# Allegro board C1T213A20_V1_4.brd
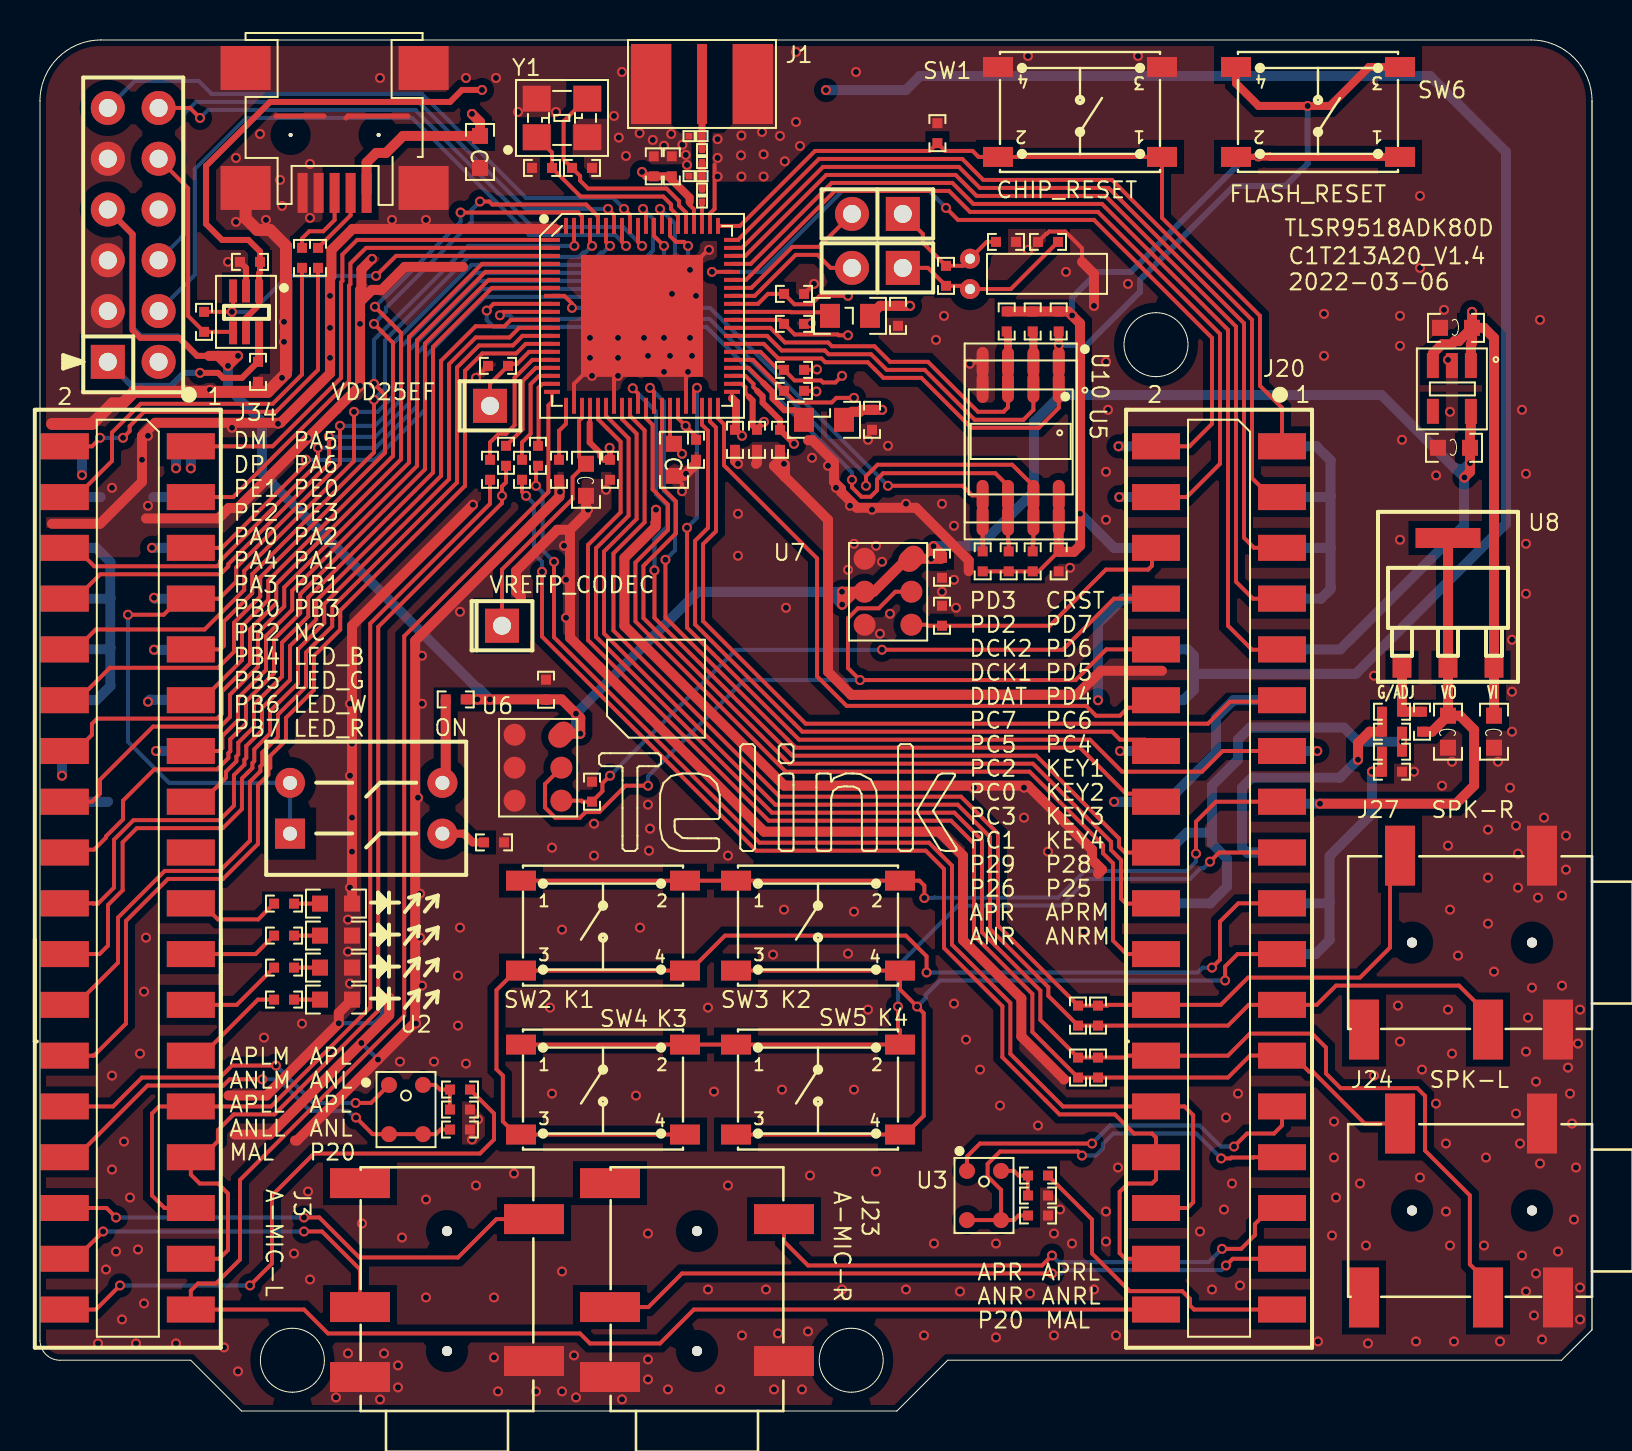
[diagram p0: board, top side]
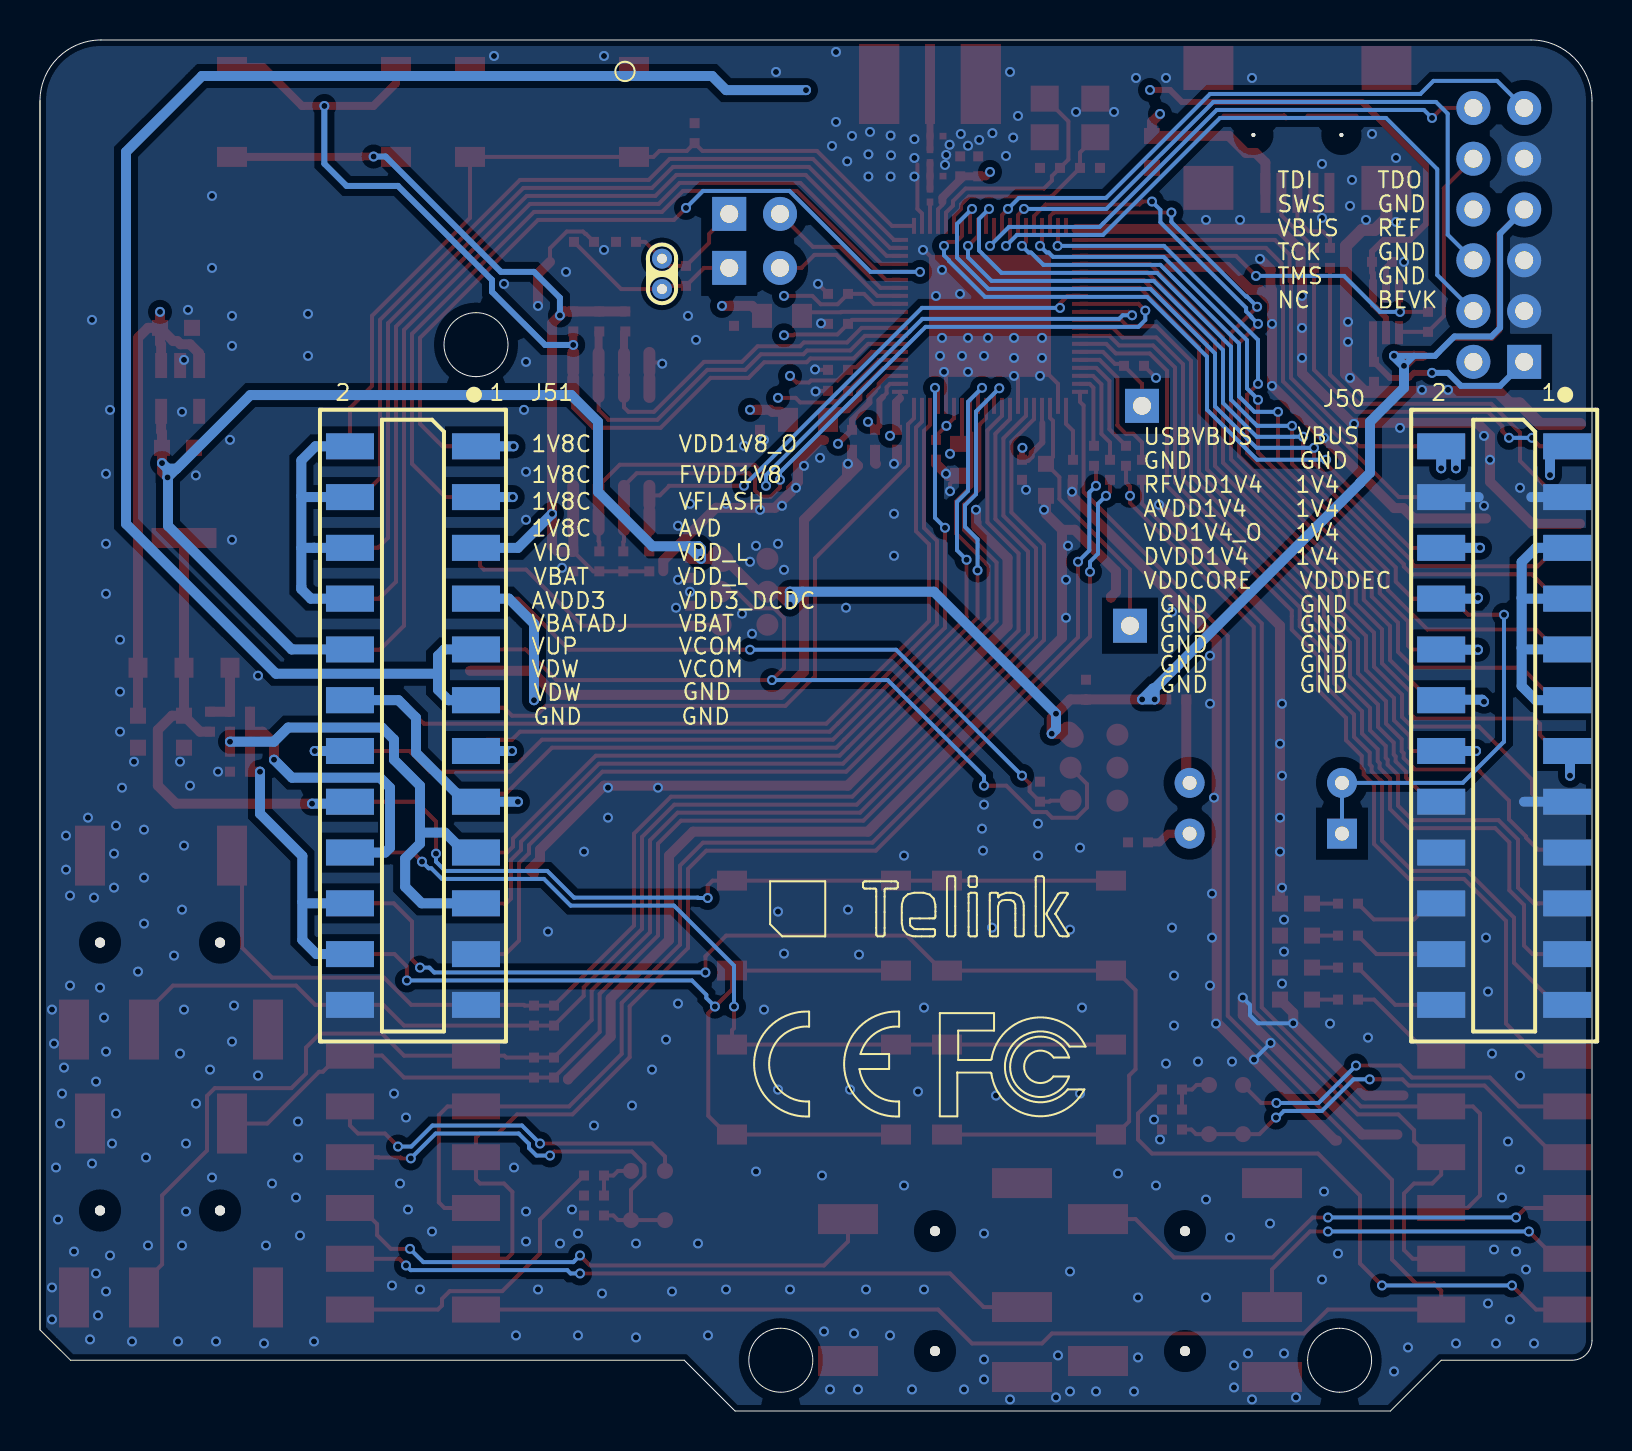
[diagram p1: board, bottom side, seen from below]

Outline 77.6 x 68.58 mm; copper layers: TOP, GND, POWER, BOTTOM. Coordinates in mm from the lower left corner of the outline.
Outline path: 77.6,65.53 arc(76.71,67.69) 74.55,68.58 3.05,68.58 arc(0.89,67.69) 0,65.53 0,3.54 arc(0.29,2.83) 1,2.54 7.54,2.54 10.08,0 42.85,0 45.39,2.54 76.08,2.54 77.6,4.06 ; 77.6,65.53 77.6,4.06 ; 77.6,65.53 77.6,4.06 ; 12.62,4.14 arc(14.22,2.54) 12.62,0.94 arc(11.02,2.54) 12.62,4.14 ; 40.56,4.14 arc(42.16,2.54) 40.56,0.94 arc(38.96,2.54) 40.56,4.14 ; 55.8,54.94 arc(57.4,53.34) 55.8,51.74 arc(54.2,53.34) 55.8,54.94

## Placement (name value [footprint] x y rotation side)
C1  NC  [0402]  27.1 62.18 180 top
C2  0.1uF  [0402]  31.59 62.26 90 top
C3  2.2uF  [0402]  30.69 62.26 90 top
C4  NC  [0402]  25.1 62.18 0 top
C6  1.8pF  [0201]  32.77 61.77 0 top
C7  1pF  [0201]  32.77 63.77 0 top
C8  NC  [0402]  50.4 58.48 0 top
C9  NC  [0402]  48.3 58.48 180 top
C10  1uF  [0402]  44.87 63.92 90 top
C11  1uF  [0402]  37.7 55.88 0 top
C12  1uF  [0402]  42.9 54.78 270 top
C13  1uF  [0402]  37.7 54.38 0 top
C14  1uF  [0402]  22.9 52.28 180 top
C15  1uF  [0402]  37 48.58 270 top
C16  1uF  [0402]  37.7 52.08 0 top
C17  1uF  [0402]  22.5 47.08 90 top
C19  1uF  [0402]  23.3 47.78 90 top
C21  1uF  [0402]  35.85 48.58 270 top
C22  1uF  [0402]  37.7 51.03 0 top
C23  0.1uF  [0402]  25.3 36.08 90 top
C24  1uF  [0402]  24.1 47.08 90 top
C25  1uF  [0402]  24.9 47.78 90 top
C26  0.1uF  [0402]  45.1 42.18 270 top
C27  1uF  [0402]  25.95 47.08 270 top
C29  1uF  [0402]  41.6 49.58 270 top
C30  10uF  [0603C]  27.3 46.58 270 top
C31  1uF  [0402]  28.5 47.08 270 top
C32  NC/10uF  [0603C]  31.7 47.58 270 top
C33  1uF  [0402]  32.8 48.08 270 top
C34  NC  [0402]  52.9 17.18 90 top
C36  10uF  [0603C]  22 62.98 270 top
C37  NC  [0402]  52.9 19.78 90 top
C38  1uF  [0402]  50.94 42.5 270 top
C39  0.1uF  [0402]  10.5 57.48 180 top
C40  0.1uF  [0402]  10.9 51.98 270 top
C41  1uF  [0402]  21 15.08 0 top
C42  1uF  [0402]  49.9 10.78 0 top
C44  10uF  [0603C]  72.7 33.98 270 top
C45  10uF  [0603C]  70.4 33.98 270 top
C48  10uF  [0603C]  70.7 48.18 180 top
C49  10uF  [0603C]  70.8 54.18 180 top
C62  1uF  [0402]  34.75 48.58 270 top
D1  Blue  [0603-LED]  14.8 25.38 0 top
D2  Green  [0603-LED]  14.8 23.78 0 top
D3  White  [0603-LED]  14.8 22.18 0 top
D4  Red  [0603-LED]  14.8 20.58 0 top
J1  RFIN  [SMA-H]  33.1 66.38 270 top
J3  AIL1  [PJ-327]  20.35 0 180 top
J20  HEADER 18X2  [SMD254M-2X18_RX1_30Y2_40]  58.95 21.59 90 top
J23  AIR1  [PJ-327]  32.85 0 180 top
J24  AOPHR  [PJ-327]  77.6 10.03 270 top
J26  USB_MiniABF  [USB-MINI-F5]  14.73 60.93 180 top
J27  AOPHR  [PJ-327]  77.6 23.43 270 top
J30  32K  [HDR254F-1X2X850]  40.6 57.18 0 top
J31  32K  [HDR254F-1X2X850]  40.6 59.88 0 top
J34  HEADER 18X2  [SMD254M-2X18_RX1_30Y2_40]  4.39 21.59 90 top
J50  HEADER 12X2  [SMD254M-2X12_RX1_30Y2_40]  4.39 34.29 90 bottom
J51  HEADER 12X2  [SMD254M-2X12_RX1_30Y2_40]  58.95 34.29 90 bottom
J52  VDD25EF  [HDR254F-1X1X850]  22.5 50.28 0 top
J53  VREFP_CODEC  [HDR254F-1X1X850]  23.1 39.28 0 top
J56  JTAG  [HDR254F-2X6X850]  3.39 65.18 270 top
J57  DIP_2X2  [DIPSWITCH_2P54_7P62_2X2]  16.31 30.15 270 top
L1  2.4nH  [0201]  33.1 62.77 90 top
L3  10uH  [0805L]  40.5 54.78 0 top
L4  10uH  [0805L]  39.2 49.58 0 top
L5  2.4nH  [0201]  33.1 60.8 90 top
R1  NC  [0402]  45.3 56.78 90 top
R2  2.2K  [0402]  21 16.08 180 top
R3  2.2K  [0402]  21 14.08 180 top
R4  2.2K  [0402]  49.9 11.78 180 top
R5  2.2K  [0402]  49.9 9.78 180 top
R6  NC  [0402]  51.9 17.18 90 top
R7  NC  [0402]  51.9 19.78 90 top
R8  33  [0402R]  13.9 57.68 270 top
R9  100K  [0402]  27.6 30.98 270 top
R10  33  [0402R]  13.1 57.68 270 top
R11  4.7K  [0402]  48.34 54.5 270 top
R12  NC  [0402]  49.64 54.5 270 top
R13  4.7K  [0402]  50.94 54.5 270 top
R14  4.7K  [0402]  49.64 42.5 90 top
R15  NC  [0402]  48.44 42.5 90 top
R16  NC  [0402]  47.14 42.5 90 top
R17  0R  [0402R]  8.2 54.48 270 top
R18  1M  [0402]  22.7 28.44 180 top
R19  100K  [0402]  45.1 39.78 270 top
R20  1K  [0402]  12.2 20.58 0 top
R21  1K  [0402]  12.2 23.78 0 top
R22  1K  [0402]  12.2 25.38 0 top
R23  1K  [0402]  12.2 22.18 0 top
R24  1K  [0402]  69.1 34.48 270 top
R25  430R  [0402]  67.6 34.98 180 top
R26  1.15K  [0402]  67.6 33.98 0 top
R27  787R  [0402]  67.6 32.98 180 top
R28  464R  [0402]  67.6 31.98 0 top
R29  1K  [0402]  20.79 35.6 180 top
SW1  SW4PIN_4.5x4.5  [SW_6X6_SMD]  52 64.98 180 top
SW2  Key1  [SW_6X6_SMD]  28.15 24.28 0 top
SW3  Key2  [SW_6X6_SMD]  38.9 24.28 0 top
SW4  Key3  [SW_6X6_SMD]  28.15 16.08 0 top
SW5  Key4  [SW_6X6_SMD]  38.9 16.08 0 top
SW6  FRST  [SW_6X6_SMD]  63.9 64.98 180 top
U1  TLSR9518A  [QFN_9X9_80PIN_0P4_6P10X6P10]  30.1 54.78 0 top
U2  WMM7037AT2  [GA_BFA423_A83]  18.3 15.08 0 top
U3  WMM7037AT2  [GA_BFA423_A83]  47.2 10.78 0 top
U4  NC/TXS0101  [SC70-6]  10.3 54.98 180 top
U5  P25Q8OU  [W25X10_20_40BL]  49.04 48.5 180 top
U6  SPM0423HM4H-WB  [DMIC_SPM0423HM4H-WB]  24.9 32.18 270 top
U7  SPM0423HM4H-WB  [DMIC_SPM0423HM4H-WB]  42.4 40.98 270 top
U8  LM1117-ADJ  [SOT-223]  70.4 40.67 0 top
U9  CE1132-33M  [SOT-23-5]  70.59 51.15 180 top
U10  NC/MX25R6435FM2IL0  [SOP8_208MIL]  49.04 48.5 180 top
Y1  24MHz-12pF-+/-20ppm  [OSCCC250X320X110]  26.1 64.68 90 top
Y2  32.768KHz - 9pf - +/-20ppm  [OSC_2X6]  50.5 56.88 180 top

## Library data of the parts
C1 C4 = C1005_NC
C2 C3 C10-C16 C21-C23 C26 C27 C29-C33 C38 C41 C42 C48 C49 C62 = C1005X5R1C104K
C6 C7 = C1608_NC: User Part Number: pn; Tolerance: RichardLC
C8 C9 = C1608_NC
C17 C19 C24 C25 C34 C37 = C1005X5R1C105K
C36 C44 = C1608X5R0J106M
C39 C40 C45 = C1608X5R1C105M
D1-D4 = 0603D_Green
J1 = SMA_JACK_2
J3 J23 J24 J27 = PJ327_2
J20 J34 = HEADER 18X2: Tolerance: RichardLC
J26 = USB_MiniABF_5pin: Tolerance: RichardLC; User Part Number: pn
J30 J31 = B2S_3: User Part Number: pn; Tolerance: RichardLC
J50 J51 = HEADER 12X2: Tolerance: RichardLC
J52 J53 = HEADER 1: User Part Number: pn; Tolerance: RichardLC
J56 = HEADER 6X2: User Part Number: pn; Tolerance: RichardLC
J57 = HEADER 2X2_0: User Part Number: pn; Tolerance: RichardLC
L1 L5 = MLK1608_000R: User Part Number: pn; Tolerance: RichardLC
L3 L4 = IND
R1 R17 = RS0603K102JT
R2-R7 R9 R11-R16 R18 R19 R29 = RS0402K104JT
R8 R10 = RS0603K330JT
R20-R23 = RS0402K102JT
R24-R28 = RS0603K104JT
SW1 = SW_6X6_SMD_0
SW2-SW6 = SW_6X6_SMD
U1 = TLSR9518A: User Part Number: pn; Tolerance: RichardLC
U2 U3 = MULPS4CX-RM5_0
U4 = TXS0101
U5 U10 = GD25LD40C_0: Tolerance: RichardLC
U6 U7 = LD1117/SO_0
U8 = XC62FP3302_0.3V_SOT-89
U9 = XC6219_6.3V_SOT-23-5
Y1 = CRYSTAL4/SM_0: Tolerance: RichardLC
Y2 = OSC_2x6_2pin_16Mhz

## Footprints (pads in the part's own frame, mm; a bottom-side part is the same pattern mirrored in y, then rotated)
0201
  rect 0.35x0.33 smd: 1(-0.325,0) 2(0.325,0)
0402
  rect 0.5x0.5 smd: 1(-0.5,0) 2(0.5,0)
0402R
  rect 0.5x0.5 smd: 1(-0.5,0) 2(0.5,0)
0603-LED
  rect 0.8x0.8 smd: A(-0.8,0) C(0.8,0)
0603C
  rect 0.8x0.8 smd: 1(-0.8,0) 2(0.8,0)
0805L
  rect 1x1.2 smd: 1(-1,0) 2(1,0)
DIPSWITCH_2P54_7P62_2X2
  rect 1.5x1.5 hole 0.7: 1(1.27,-3.81)
  round 1.5 hole 0.7: 2(1.27,3.81) 3(-1.27,-3.81) 4(-1.27,3.81)
DMIC_SPM0423HM4H-WB
  round 1.1 smd: 1(-1.65,-1.17) 2(0,-1.17) 3(1.65,-1.17) 4(1.65,1.17) 5(0,1.17)
  oval 1.4x1.1 smd rot 135: 6(-1.65,1.17)
GA_BFA423_A83
  round 0.8 smd: 1(-0.85,1.23) 2(-0.85,-1.23) 3(0.85,-1.23) 4(0.85,1.23)
HDR254F-1X1X850
  rect 1.7x1.7 hole 0.9: 1(0,0)
HDR254F-1X2X850
  rect 1.7x1.7 hole 0.9: 1(2.54,0)
  round 1.7 hole 0.9: 2(0,0)
HDR254F-2X6X850
  rect 1.7x1.7 hole 0.9: 1(12.7,0)
  round 1.7 hole 0.9: 2(12.7,2.54) 3(10.16,0) 4(10.16,2.54) 5(7.62,0) 6(7.62,2.54) 7(5.08,0) 8(5.08,2.54) 9(2.54,0) 10(2.54,2.54) 11(0,0) 12(0,2.54)
OSC_2X6
  round 1 hole 0.5: 1(4,0.76) 2(4,-0.76)
OSCCC250X320X110
  rect 1.3x1.4 smd: 1(-0.965,1.265) 2(-0.965,-1.265) 3(0.965,-1.265) 4(0.965,1.265)
PJ-327
  round 0.5 hole 1: (0,-3) (0,-9)
  rect 3x1.5 smd: 1(-4.35,-2.5) 2(4.35,-5.2) 3(-4.35,-9.6) 4(4.35,-11.4) 5(4.35,-1.7)
QFN_9X9_80PIN_0P4_6P10X6P10
  rect 0.8x0.2 smd: 1(-4.5,3.8) 2(-4.5,3.4) 3(-4.5,3) 4(-4.5,2.6) 5(-4.5,2.2) 6(-4.5,1.8) 7(-4.5,1.4) 8(-4.5,1) 9(-4.5,0.6) 10(-4.5,0.2) 11(-4.5,-0.2) 12(-4.5,-0.6) 13(-4.5,-1) 14(-4.5,-1.4) 15(-4.5,-1.8) 16(-4.5,-2.2) 17(-4.5,-2.6) 18(-4.5,-3) 19(-4.5,-3.4) 20(-4.5,-3.8) 41(4.5,-3.8) 42(4.5,-3.4) 43(4.5,-3) 44(4.5,-2.6) 45(4.5,-2.2) 46(4.5,-1.8) 47(4.5,-1.4) 48(4.5,-1) 49(4.5,-0.6) 50(4.5,-0.2) 51(4.5,0.2) 52(4.5,0.6) 53(4.5,1) 54(4.5,1.4) 55(4.5,1.8) 56(4.5,2.2) 57(4.5,2.6) 58(4.5,3) 59(4.5,3.4) 60(4.5,3.8)
  rect 0.2x0.8 smd: 21(-3.8,-4.5) 22(-3.4,-4.5) 23(-3,-4.5) 24(-2.6,-4.5) 25(-2.2,-4.5) 26(-1.8,-4.5) 27(-1.4,-4.5) 28(-1,-4.5) 29(-0.6,-4.5) 30(-0.2,-4.5) 31(0.2,-4.5) 32(0.6,-4.5) 33(1,-4.5) 34(1.4,-4.5) 35(1.8,-4.5) 36(2.2,-4.5) 37(2.6,-4.5) 38(3,-4.5) 39(3.4,-4.5) 40(3.8,-4.5) 61(3.8,4.5) 62(3.4,4.5) 63(3,4.5) 64(2.6,4.5) 65(2.2,4.5) 66(1.8,4.5) 67(1.4,4.5) 68(1,4.5) 69(0.6,4.5) 70(0.2,4.5) 71(-0.2,4.5) 72(-0.6,4.5) 73(-1,4.5) 74(-1.4,4.5) 75(-1.8,4.5) 76(-2.2,4.5) 77(-2.6,4.5) 78(-3,4.5) 79(-3.4,4.5) 80(-3.8,4.5)
  rect 6.1x6.1 smd: 81(0,0)
SC70-6
  rect 0.4x1.15 smd: 1(-0.65,-1.045) 2(0,-1.045) 3(0.65,-1.045) 4(0.65,1.045) 5(0,1.045) 6(-0.65,1.045)
SMA-H
  rect 4x0.5 smd: 1(0,0)
  rect 4x2 smd: 2(0,-2.54) 3(0,2.54) 4(0,-2.54) 5(0,2.54)
SMD254M-2X12_RX1_30Y2_40
  rect 1.3x2.4 smd: 1(13.97,-3.15) 2(13.97,3.15) 3(11.43,-3.15) 4(11.43,3.15) 5(8.89,-3.15) 6(8.89,3.15) 7(6.35,-3.15) 8(6.35,3.15) 9(3.81,-3.15) 10(3.81,3.15) 11(1.27,-3.15) 12(1.27,3.15) 13(-1.27,-3.15) 14(-1.27,3.15) 15(-3.81,-3.15) 16(-3.81,3.15) 17(-6.35,-3.15) 18(-6.35,3.15) 19(-8.89,-3.15) 20(-8.89,3.15) 21(-11.43,-3.15) 22(-11.43,3.15) 23(-13.97,-3.15) 24(-13.97,3.15)
SMD254M-2X18_RX1_30Y2_40
  rect 1.3x2.4 smd: 1(26.67,-3.15) 2(26.67,3.15) 3(24.13,-3.15) 4(24.13,3.15) 5(21.59,-3.15) 6(21.59,3.15) 7(19.05,-3.15) 8(19.05,3.15) 9(16.51,-3.15) 10(16.51,3.15) 11(13.97,-3.15) 12(13.97,3.15) 13(11.43,-3.15) 14(11.43,3.15) 15(8.89,-3.15) 16(8.89,3.15) 17(6.35,-3.15) 18(6.35,3.15) 19(3.81,-3.15) 20(3.81,3.15) 21(1.27,-3.15) 22(1.27,3.15) 23(-1.27,-3.15) 24(-1.27,3.15) 25(-3.81,-3.15) 26(-3.81,3.15) 27(-6.35,-3.15) 28(-6.35,3.15) 29(-8.89,-3.15) 30(-8.89,3.15) 31(-11.43,-3.15) 32(-11.43,3.15) 33(-13.97,-3.15) 34(-13.97,3.15) 35(-16.51,-3.15) 36(-16.51,3.15)
SOP8_208MIL
  oval 0.6x1.55 smd: 1(-1.905,-3.95) 2(-0.635,-3.95) 3(0.635,-3.95) 4(1.905,-3.95) 5(1.905,3.95) 6(0.635,3.95) 7(-0.635,3.95) 8(-1.905,3.95)
SOT-23-5
  rect 0.6x1.25 smd: 1(-0.95,-1.145) 2(0,-1.145) 3(0.95,-1.145) 4(0.95,1.145) 5(-0.95,1.145)
SOT-223
  rect 0.95x1 smd: 1(-2.3,-3.495) 2(0,-3.495) 3(2.3,-3.495)
  rect 3.25x1 smd: 4(0,2.995)
SW_6X6_SMD
  rect 1.5x1 smd: 1(-4.1,2.25) 2(4.1,2.25) 3(-4.1,-2.25) 4(4.1,-2.25)
USB-MINI-F5
  round 0.2 hole 0.9 unplated: (-2.2,-2.9) (2.2,-2.9)
  rect 0.5x2 smd: 1(-1.6,0) 2(-0.8,0) 3(0,0) 4(0.8,0) 5(1.6,0)
  rect 2.5x2.2 smd: 6(-4.45,-6.25) 7(4.45,-6.25) 8(-4.45,-0.25) 9(4.45,-0.25)
W25X10_20_40BL
  oval 0.6x1.55 smd: 1(-1.905,-2.7) 2(-0.635,-2.7) 3(0.635,-2.7) 4(1.905,-2.7) 5(1.905,2.7) 6(0.635,2.7) 7(-0.635,2.7) 8(-1.905,2.7)

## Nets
VBUS: C36.1 C44.1 C49.1 J26.1(V_BUS) J50.2 J56.8 U8.3(VIN) U9.1(VIN) U9.3(CE)
VDD_L: C39.1 J51.9 J51.11 U4.1(VCCA) U4.5(OE)
0: C1.1 C2.2 C3.2 C4.1 C6.1 C7.1 C8.1 C9.1 C10.2 C11.2 C12.2 C13.2 C14.2 C15.2 C16.2 C21.2 C22.2 C23.2 C26.2 C27.2 C29.2 C30.2 C31.2 C32.2 C33.2 C36.2 C38.2 C39.2 C40.2 C41.2 C42.2 C44.2 C45.2 C48.2 C49.2 C62.2 D1.C(CATHODE) D2.C(CATHODE) D3.C(CATHODE) D4.C(CATHODE) J1.2 J1.3 J1.4 J1.5 J3.1 J3.5 J23.1 J23.5 J24.1 J24.5 J26.4(ID) J26.5(GND) J26.6(S1) J26.7(S2) J26.8(S3) J26.9(S4) J27.1 J27.5 J50.3 J50.4 J50.15 J50.16 J50.17 J50.18 J50.19 J50.20 J50.21 J50.22 J50.23 J50.24 J51.21 J51.23 J51.24 J56.3 J56.5 J56.9 R3.1 R5.1 R9.1 R18.1 R19.1 R28.2 SW1.3 SW1.4 U1.22(VSSA) U1.27(VSSAO) U1.36(DVSS) U1.62(GANT) U1.81(GND) U4.2(GND) U5.4(VSS) U6.1(GND#1) U6.2(SE) U6.3(GND#3) U7.1(GND#1) U7.3(GND#3) U9.2(VSS) U10.4(VSS) Y1.2 Y1.4
AINL1_LINEIN: J3.2 J34.34
AINL1_MIC: J34.30 R3.2 U2.2(GND#2) U2.3(GND#3)
AINR1_LINEIN: J20.33 J23.2
AINR1_MIC: J20.29 R5.2 U3.2(GND#2) U3.3(GND#3)
AIPL1_LINEIN: J3.3 J34.32
AIPL1_MIC: J34.28 U2.1(OUTPUT)
AIPR1_LINEIN: J20.31 J23.3
AIPR1_MIC: J20.27 U3.1(OUTPUT)
BEVK_3V3: C40.1 J56.1 U4.6(VCCB)
BEVK_SWS: J56.10 R17.2 U4.4(B)
DM: J34.2 R8.2
DMICCK1: J20.8 R9.2 U6.4(CLOCK)
DMICCK2: J20.6 R19.2 U7.4(CLOCK)
DMICDAT: J20.10 U6.5(DATA) U7.5(DATA)
DP: J34.4 R10.2
LED_B: J34.19 R22.1
LED_G: J34.21 R21.1
LED_R: J34.25 R20.1
LED_W: J34.23 R23.1
MICBIAS_AIL1: J34.36 R2.1
MICBIAS_AIR1: J20.35 R4.1
TL_AINL1: C19.1 J34.29 J34.33
TL_AINR1: C24.1 J20.30 J20.34
TL_AIPL1: C17.1 J34.27 J34.31
TL_AIPR1: C25.1 J20.28 J20.32
TL_AONHPL: C34.2 J20.26 J24.2 R6.2 U1.26(AONHPL)
TL_AONHPR: C37.1 J20.23 J27.2 R7.1 U1.28(AONHPR)
TL_AOPHPL: C34.1 J20.25 J24.3 R6.1 U1.25(AOPHPL)
TL_AOPHPR: C37.2 J20.24 J27.3 R7.2 U1.29(AOPHPR)
TL_AVD: C31.1 J51.7 U1.24(AVD)
TL_AVDD1V4: C16.1 J50.8 U1.46(AVDD1V4)
TL_AVDD3: C11.1 J51.14 U1.52(AVDD3)
TL_DVDD1V4: C22.1 J50.12 U1.45(DVDD1V4)
TL_FLASH: C38.1 J51.5 R11.1 R12.1 R13.1 R14.1 R15.1 R16.1 SW6.1 SW6.2 U5.8(VCC) U10.8(VCC)
TL_FVDD1V8: C13.1 J51.3 U1.50(FVDD1V8)
TL_IO: C23.1 C26.1 C48.1 J51.10 J56.7 R29.1 U6.6(POWER) U7.2(SE) U7.6(POWER) U9.5(VOUT)
TL_KEY1: J20.15 SW2.1 SW2.2 SW3.1 SW3.2
TL_KEY2: J20.17 SW4.1 SW4.2 SW5.1 SW5.2
TL_KEY3: J20.19 SW2.3 SW2.4 SW4.3 SW4.4
TL_KEY4: J20.21 SW3.3 SW3.4 SW5.3 SW5.4
TL_MICBIAS: J20.36 J34.35 U1.20(MICBIAS1)
TL_PA0_I2SCLK: J34.10 U1.75(PA[0])
TL_PA1_SPI_SLV_CN: J34.11 U1.76(PA[1])
TL_PA2_SPI_SLV_CK: J34.9 U1.77(PA[2])
TL_PA3_SPI_SLV_DI: J34.14 U1.78(PA[3])
TL_PA4_SPI_SLV_DO: J34.12 U1.79(PA[4])
TL_PA5_DM: J34.1 U1.1(PA[5])
TL_PA6_DP: J34.3 U1.2(PA[6])
TL_PA7_SWS: R17.1 U1.3(PA[7]) U4.3(A)
TL_PB0: J34.16 U1.4(PB[0])
TL_PB1: J34.13 U1.5(PB[1])
TL_PB2_I2CSCK: J34.18 U1.6(PB[2])
TL_PB3_I2CSDA: J34.15 U1.7(PB[3])
TL_PB4: J34.20 U1.11(PB[4])
TL_PB5: J34.22 U1.12(PB[5])
TL_PB6: J34.24 U1.13(PB[6])
TL_PB7: J34.26 U1.14(PB[7])
TL_PC0: J20.18 U1.30(PC[0])
TL_PC1: J20.22 U1.31(PC[1])
TL_PC2: J20.16 U1.32(PC[2])
TL_PC3_I2SBCK: J20.20 U1.33(PC[3])
TL_PC4_ADC_LR: J20.13 U1.37(PC[4])
TL_PC5_ADC_DAT: J20.14 U1.38(PC[5])
TL_PC6_DAC_LR: J20.11 U1.39(PC[6])
TL_PC7_DAC_DAT: J20.12 U1.40(PC[7])
TL_PD0_32K: J30.2 U1.53(PD[0])
TL_PD1_32K: J31.2 U1.54(PD[1])
TL_PD2: J20.4 U1.55(PD[2])
TL_PD3: J20.2 U1.56(PD[3])
TL_PD4_DMICDAT: J20.9 U1.57(PD[4])
TL_PD5_DMICCLK1: J20.7 U1.58(PD[5])
TL_PD6_DMICCLK2: J20.5 U1.59(PD[6])
TL_PD7: J20.3 U1.60(PD[7])
TL_PE0_UART1_TX: J34.5 U1.67(PE[0])
TL_PE1_UART1_CTS: J34.6 U1.68(PE[1])
TL_PE2_UART1_RTX: J34.8 U1.69(PE[2])
TL_PE3_UART1_RTS: J34.7 J57.1 J57.3 U1.70(PE[3])
TL_PE4_TDI: J56.12 U1.71(PE[4])
TL_PE5_TDO: J56.11 U1.72(PE[5])
TL_PE6_TMS: J56.4 U1.73(PE[6])
TL_PE7_TCK: J56.6 U1.74(PE[7])
TL_PF0_MOSI: R16.2 U1.8(PF[0]) U5.5(SI/IO0) U10.5(SI/IO0)
TL_PF1_MCLK: R15.2 U1.9(PF[1]) U5.6(SCLK) U10.6(SCLK)
TL_PF2_MSIO3: R14.2 U1.10(PF[2]) U5.7(HOLD/IO3) U10.7(HOLD/IO3)
TL_PF3_MSCN: R13.2 SW6.3 SW6.4 U1.47(PF[3]) U5.1(C\S\) U10.1(C\S\)
TL_PF4_MISO: R12.2 U1.48(PF[4]) U5.2(SO/IO1) U10.2(SO/IO1)
TL_PF5_MSIO2: R11.2 U1.49(PF[5]) U5.3(W\P\/IO2) U10.3(W\P\/IO2)
TL_RFVDD1V4: C2.1 C3.1 J50.6 U1.64(VLINE_PAD)
TL_RST: C10.1 J20.1 SW1.1 SW1.2 U1.61(RESETB)
TL_VBAT: C21.1 J51.12 J51.15 U1.42(VBAT)
TL_VBAT_ADJ: C45.1 J51.16 R24.2 U8.2(VOUT#2) U8.4(VOUT#4)
TL_VBUS: C62.1 J50.1 U1.41(VBUS)
TL_VDD1V4_O: C29.1 J50.10 L4.2
TL_VDD1V8_O: C12.1 J51.1 L3.2
TL_VDD3_DCDC: C15.1 J51.13 U1.43(VDD3_DCDC)
TL_VDD25EF: C14.1 J52.1 U1.15(VDD25EF)
TL_VDDCORE: C32.1 J50.14 U1.34(VDDCORE)
TL_VDDDEC: C33.1 J50.13 U1.35(VDDDEC)
TL_XC1: C1.2 U1.65(XC1) Y1.3
TL_XC2: C4.2 U1.66(XC2) Y1.1
VCOM: J51.17 J51.19 R26.2 R27.1
VDW: J51.20 J51.22 R27.2 R28.1
VUP: J51.18 R25.2 R26.1
N19754780: J26.3(D+) R10.1
N19754798: J26.2(D-) R8.1
N19860865: C8.2 J30.1 R1.1 Y2.1
N19860867: C9.2 J31.1 R1.2 Y2.2
N19861195: C24.2 U1.18(AINR1)
N19861200: C25.2 U1.19(AIPR1)
N19861219: C30.1 J53.1 U1.23(VREFP_CODEC)
N19861425: C19.2 U1.17(AINL1)
N19861431: C17.2 U1.16(AIPL1)
N19861467: C27.1 U1.21(VCAP)
N19861531: L3.1 U1.51(VDD1V8_O)
N19861571: L4.1 U1.44(VDD1V4_O)
N19870648: R24.1 R25.1 U8.1(ADJ)
N19912632: C42.1 R4.2 U3.4(VDD)
N19912698: C41.1 R2.2 U2.4(VDD)
N19916631: J57.4 R29.2
N19927561: J50.5 J50.7 J50.9 J50.11
N19931796: J51.2 J51.4 J51.6 J51.8
N19937731: J57.2 R18.2
N19956971: L5.1 U1.63(ANT)
N19973210: C7.2 J1.1 L1.2
N19973218: C6.2 L1.1 L5.2
N198520641: D4.A(ANODE) R20.2
N198520720: D1.A(ANODE) R22.2
N198520801: D2.A(ANODE) R21.2
N198520880: D3.A(ANODE) R23.2

Pads without a net: J3 4; J23 4; J24 4; J27 4; J34 17; J56 2; U1 80; U9 4

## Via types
v1: diameter 0.5, hole 0.3, TOP to BOTTOM, 492 vias

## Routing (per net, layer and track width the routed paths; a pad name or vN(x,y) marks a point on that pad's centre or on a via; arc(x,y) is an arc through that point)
VBUS: length 37.7
  TOP w0.5: C49.1 72.2,54.18 72.7,53.68 U8.3 C44.1 ; C49.1 v1(71.6,54.98) ; C49.1 71.6,53.41 71.55,53.35 U9.1 ; C49.1 70.94,53.52 70.73,53.52 70.57,53.36 70.1,53.36 69.64,52.91 U9.3 ; J26.1 16.33,62.45 16.81,62.93 17.3,62.93 18.15,63.78 C36.1 22,64.48 v1(21.6,64.88)
  BOTTOM w0.2: 6.8,47.88 6.8,47.58
  BOTTOM w0.5: 6.8,47.88 7.18,48.26 J50.2 v1(7.54,47.16) ; 6.8,47.58 v1(6.8,47.16)
VDD_L: length 104.9
  TOP w0.3: U4.5 10.3,54.68 10.95,55.33 U4.1 10.95,56.91 11,56.96 C39.1 11,58 10.42,58.58 9.1,58.58 8.3,59.38 8.3,62.28 11.5,65.48 20.5,65.48 21.1,66.08 v1(22.1,66.08)
  BOTTOM w0.5: 57.7,36.88 65.8,36.88 73.3,44.38 73.3,62.98 69.5,66.78 44,66.78 43.29,66.07 v1(39.3,66.07) ; 57.7,36.88 57.7,37.78 57.38,38.1 J51.9 ; 57.7,36.88 57.7,36.08 57.18,35.56 J51.11
0: length 349.4
  TOP w0.2: U1.81 v1(31.2,53.68) 32.3,52.58 U1.36 ; U1.81 28.7,53.38 ; U1.81 33.5,58.18 ; v1(38.82,51) 38.6,51 38.57,51.03 C22.2 ; C8.1 50.31,58.89 50.34,58.89 50.45,59 51.26,59 52.1,58.16 52.1,57.48 ; U1.22 26.7,51.38 28.7,53.38 ; C32.2 32.1,46.38 v1(32.1,46.01) ; 28.7,53.38 U1.27 ; 33.73,62.36 33.73,60.13 33.5,59.9 U1.62 ; v1(38.55,54.41) 38.53,54.41 38.5,54.38 C13.2 ; C11.2 v1(38.7,56.38) ; v1(38.85,52.1) 38.83,52.08 C16.2 ; C14.2 v1(21.8,51.68) ; U10.4 46.55,52.45 v1(46.49,52.39) ; v1(37.2,47.38) 37,47.58
  TOP w0.25: 15.3,64.68 15.4,64.78 18.4,64.78 ; 14.2,64.78 11.8,64.78
  TOP w0.3: C39.2 10.3,57.18 U4.2
  TOP w0.4: U10.4 U5.4
  TOP w0.5: 37.25,46.73 39.4,44.58 39.4,36.98 40.56,35.82 51.84,35.82 53.05,37.03 56.1,37.03 ; 37.25,46.73 37.25,47.33 v1(37.2,47.38) ; 37.25,46.73 36.7,47.28 37,47.58 C15.2 ; D1.C v1(15.6,27.98) v1(15.6,29.68) v1(15.6,33.38) 15.6,39.28 19.31,42.99 20.31,44 v1(21.65,45.33) ; 12.75,13.53 12.85,13.53 v1(16.9,17.58) 18.76,19.44 18.76,38.53 25.97,45.74 25.97,46.58 ; 0.6,44.38 3,44.38 5.1,46.48 v1(5.1,47.58) 5.1,48.78 5.75,49.43 12.03,49.43 14.5,51.9 v1(14.5,52.68) v1(14.5,54.18) v1(14.5,55.78) 14.5,56.69 14.57,56.76 14.57,58.07 15.63,59.13 25.78,59.13 ; C62.2 34.75,47.53 v1(34.9,47.38) ; 26.5,44.08 27.3,44.88 C30.2 ; 26.5,44.08 25.87,44.08 23.8,42.01 23.8,40.98 24.05,40.73 24.05,40.68 ; 26.5,44.08 26.5,38.68 36.2,28.98 44.95,28.98 46.15,27.78 46.15,23.55 49.07,20.64 49.07,18.73 51.2,16.6 51.2,16.58 ; v1(30.8,45.08) 30.8,44.48 30.78,44.46 30.78,44.23 29.22,42.67 29.22,39.27 37.21,31.28 49.4,31.28 52.6,28.08 52.6,27.58 53.1,27.08 52.9,26.88 ; 9.42,15.79 11.33,15.79 v1(14.94,19.4) 14.94,19.92 D4.C ; 52.1,57.48 52.7,56.88 v1(52.7,55.28) ; 38.4,48.56 38.62,48.56 39.7,47.48 39.7,46.48 40.05,46.13 40.05,45.97 40.84,45.18 43.8,45.18 46.44,42.54 46.44,42.01 ; v1(17.46,20.68) 17.46,19.8 v1(16.07,18.41) 11.49,13.83 9.73,13.83 ; C32.2 32.2,46.78 v1(32.3,46.88) 32.8,47.38 C33.2 ; 35.8,47.38 35.85,47.43 C21.2 ; 5.3,44.65 8.92,44.65 9.44,45.17 9.88,45.17 v1(16,51.28) v1(16,54.38) 16,55.48 ; 16,55.48 16.6,56.08 17.09,56.08 18.24,57.23 21.15,57.23 ; 16,55.48 16,56.06 16.07,56.13 16.07,57.1 v1(16.6,57.63)
  TOP w0.6: J26.9 10.28,59.66 10.86,59.08 11.5,59.08 12.3,58.28 12.3,51.89 11.39,50.98 4.7,50.98 4.12,50.4 3.62,50.4 2.6,49.38 0.6,49.38
  BOTTOM w0.2: v1(14.94,19.4) 16.7,19.4 17.1,19.8 17.1,20.32 v1(17.46,20.68) ; v1(16.07,18.41) v1(16.9,17.58)
  BOTTOM w0.5: J50.3 3.04,45.72 ; J50.4 5.66,45.72 ; J50.15 3.4,30.48
  vias: v1(2.9,3.38) v1(3.3,7.08) v1(3.6,46.18) v1(3.6,16.78) v1(3.6,12.08) v1(3.8,7.98) v1(4.1,4.58) v1(4.2,13.48) v1(4.5,10.68) v1(4.8,3.38) v1(4.9,8.08) v1(5,17.88) v1(5.2,20.98) v1(5.2,5.38) v1(5.3,23.68) v1(5.4,48.78) v1(5.4,45.28) v1(6.8,3.38) v1(7.2,51.08) v1(8.5,51.08) v1(9.2,3.18) v1(9.4,57.48) v1(9.6,49.18) v1(9.8,62.68) v1(9.8,59.48) v1(9.9,1.98) v1(11,63.88) v1(11.2,18.68) v1(11.3,59.58) v1(11.9,49.38) v1(12,61.58) v1(12.1,60.28) v1(12.1,51.68) v1(12.2,54.48) v1(12.2,53.48) v1(12.7,7.88) v1(13.1,19.38) v1(13.4,48.68) v1(13.4,10.98) v1(13.5,62.38) v1(13.5,59.68) v1(13.5,6.58) v1(14.8,0.68) v1(15.4,24.58) v1(15.4,22.98) v1(15.4,2.88) v1(15.5,35.38) v1(15.5,31.78) v1(15.5,26.18) v1(15.5,21.38) v1(16.1,9.38) v1(17,66.68) v1(17,0.58) v1(17.2,2.88) v1(17.6,59.58) v1(17.9,2.28) v1(17.9,1.18) v1(18,17.48) v1(18.1,8.68) v1(18.8,19.38) v1(18.9,30.68) v1(19,25.88) v1(19,23.68) v1(19.1,37.78) v1(19.1,35.38) v1(19.1,21.28) v1(19.3,59.58) v1(19.3,10.58) v1(19.3,5.68) v1(19.7,17.48) v1(20.9,21.78) v1(20.9,19.28) v1(21,39.98) v1(21,24.18) v1(21.3,66.68) v1(21.3,17.38) v1(21.6,13.58) v1(21.8,11.28) v1(21.9,14.58) v1(22.7,5.68) v1(22.7,2.68) v1(22.8,66.68) v1(22.9,0.98) v1(23.7,11.88) v1(23.9,64.98) v1(24.8,0.98) v1(25.5,20.18) v1(25.6,28.18) v1(25.6,15.88) v1(25.8,64.98) v1(26,45.98) v1(26.1,24.08) v1(26.1,6.98) v1(26.1,0.98) v1(26.2,43.28) v1(26.3,41.58) v1(26.3,39.68) v1(26.7,2.78) v1(26.8,0.68) v1(27.4,45.08) v1(27.5,53.68) v1(27.5,52.68) v1(27.6,51.78) v1(27.7,29.38) v1(27.7,27.78) v1(28.3,46.08) v1(28.7,64.78) v1(28.94,63.7) v1(28.9,53.68) v1(28.9,52.68) v1(28.9,51.78) v1(29.1,66.98) v1(29.1,0.58) v1(29.3,62.78) v1(29.8,15.78) v1(29.98,63.92) v1(30,24.18) v1(30.2,53.68) v1(30.4,52.78) v1(30.4,30.33) v1(30.45,28.03) v1(30.4,8.88) v1(30.4,2.58) v1(30.4,1.58) v1(30.5,29.13) v1(30.64,63.58) v1(31.2,63.29) v1(31.2,51.98) v1(31.4,1.08) v1(31.5,52.78) v1(31.56,63.88) v1(31.6,55.88) v1(32.12,63.34) v1(32.29,62.83) v1(32.35,62.33) v1(32.4,51.98) v1(32.5,57.08) v1(32.5,53.68) v1(32.6,52.78) v1(32.8,55.78) v1(33.4,20.18) v1(33.4,6.08) v1(33.45,58.08) v1(33.7,15.98) v1(33.88,63.62) v1(33.88,62.68) v1(33.88,61.75) v1(34,1.08) v1(34.4,27.78) v1(34.4,11.28) v1(34.9,44.88) v1(34.9,42.78) v1(35.05,62.81) v1(35.07,63.8) v1(35.07,61.75) v1(35.1,3.78) v1(36.1,63.98) v1(36.18,62.86) v1(36.18,61.75) v1(36.3,6.08) v1(36.65,22.83) v1(36.7,1.08) v1(36.9,3.88) v1(37,63.78) v1(37.1,16.08) v1(37.24,62.51) v1(37.2,25.08) v1(37.3,40.18) v1(37.8,67.98) v1(37.8,64.48) v1(38,63.28) v1(38.1,1.08) v1(38.4,3.98) v1(38.5,11.78) v1(38.6,47.68) v1(39.4,47.28) v1(39.8,46.18) v1(40.1,6.08) v1(40.4,42.08) v1(40.4,22.88) v1(40.5,45.28) v1(40.7,43.38) v1(40.7,24.98) v1(40.7,16.08) v1(40.8,66.98) v1(41.4,48.58) v1(41.4,20.08) v1(41.6,45.08) v1(41.8,43.28) v1(41.8,11.98) v1(42,38.88) v1(42.1,42.48) v1(42.4,48.28) v1(42.5,39.88) v1(43.3,45.38) v1(43.3,6.08) v1(44.2,3.78) v1(44.7,8.38) v1(44.8,53.58) v1(45.1,45.38) v1(45.1,40.98) v1(45.2,54.78) v1(45.7,44.28) v1(45.7,41.58) v1(45.7,20.38) v1(45.8,40.18) v1(46,5.98) v1(46.3,18.58) v1(46.7,31.18) v1(47,17.08) v1(47.8,8.38) v1(47.8,3.68) v1(48,15.28) v1(49.2,31.18) v1(49.2,29.68) v1(49.4,67.78) v1(49.4,58.08) v1(49.5,5.88) v1(49.9,14.28) v1(50.4,27.98) v1(50.7,8.88) v1(50.7,3.78) v1(51,10.08) v1(51.3,56.98) v1(51.5,42.18) v1(51.6,8.38) v1(52.2,23.98) v1(52.7,6.08) v1(53.3,52.48) v1(53.3,46.98) v1(53.3,44.58) v1(53.3,9.98) v1(53.3,8.48) v1(53.4,50.08) v1(53.8,3.78) v1(53.9,12.18) v1(54.4,56.38) v1(54.9,67.78) v1(58,8.98) v1(58.6,6.08) v1(59.2,10.08) v1(59.3,14.68) v1(59.6,11.38) v1(59.9,15.88) v1(60,6.28) v1(63.9,3.48) v1(64.2,54.88) v1(64.2,52.78) v1(64.6,8.78) v1(64.7,14.48) v1(64.7,12.68) v1(64.8,10.68) v1(66,11.38) v1(66.3,8.28) v1(66.4,3.38) v1(66.7,36.78) v1(66.7,16.78) v1(67.9,20.28) v1(68,54.78) v1(68,53.28) v1(68,43.58) v1(68,18.48) v1(68.1,48.58) v1(68.7,31.98) v1(68.8,3.48) v1(69,60.78) v1(69,57.18) v1(69,11.68) v1(69.1,17.08) v1(69.81,46.8) v1(69.8,15.38) v1(70.1,31.28) v1(70.2,55.08) v1(70.3,13.38) v1(70.3,9.98) v1(70.4,52.58) v1(70.4,28.28) v1(70.4,20.08) v1(70.5,49.98) v1(70.5,25.08) v1(70.5,8.28) v1(70.6,32.48) v1(70.6,17.88) v1(70.7,3.48) v1(70.9,22.78) v1(72.2,8.28) v1(72.3,12.68) v1(72.4,29.08) v1(72.4,26.68) v1(72.4,24.38) v1(72.7,21.98) v1(72.9,32.48) v1(73,3.48) v1(73.5,31.18) v1(73.6,38.58) v1(73.6,35.98) v1(73.6,33.98) v1(73.8,29.28) v1(73.8,14.88) v1(73.9,27.88) v1(73.9,26.18) v1(74,13.38) v1(74.1,50.08) v1(74.1,7.78) v1(74.3,46.88) v1(74.3,43.38) v1(74.3,40.88) v1(74.3,17.98) v1(74.3,5.98) v1(74.4,19.68) v1(74.6,21.18) v1(74.7,4.78) v1(74.8,16.48) v1(74.8,6.88) v1(74.9,25.68) v1(75,54.58) v1(75,12.38) v1(75.1,3.58) v1(75.2,29.68) v1(75.9,7.98) v1(76.1,25.78) v1(76.1,21.28) v1(76.3,28.78) v1(76.3,27.08) v1(76.4,17.18) v1(76.5,15.88) v1(76.6,14.38) v1(76.7,9.58) v1(76.8,12.18) v1(76.9,18.38) v1(77,20.08) v1(77,6.18) v1(77,4.58)
AINL1_LINEIN: length 18
  TOP w0.2: v1(13.2,8.98) 14.1,8.98 16,7.08 J3.2 ; J34.34 1.79,7.62 v1(3.16,8.98)
  BOTTOM w0.2: v1(13.2,8.98) v1(3.16,8.98)
AINL1_MIC: length 22.1
  TOP w0.2: J34.30 1.79,12.7 5.38,16.28 9.17,16.28 9.48,16.59 v1(11.12,16.59) ; v1(15.8,14.68) 16.63,13.85 U2.2 U2.3 19.8,13.85 20.03,14.08 R3.2
  BOTTOM w0.2: v1(15.8,14.68) 15.73,14.68 15.4,15.01 13.5,15.01 11.92,16.59 v1(11.12,16.59)
AINR1_LINEIN: length 34.6
  TOP w0.2: v1(59.3,7.28) 59.64,7.62 J20.33 ; v1(50.6,6.88) 32.1,6.88 30.42,5.2 J23.2
  BOTTOM w0.2: v1(50.6,6.88) 51.07,6.88 51.24,7.05 59.07,7.05 v1(59.3,7.28)
AINR1_MIC: length 22.4
  TOP w0.2: U3.3 48.7,9.55 48.93,9.78 R5.2 ; U3.3 48.05,11.06 47.38,11.73 47.38,12.36 48,12.98 51.9,12.98 v1(52.1,12.78) ; U3.3 U3.2 ; v1(59.06,12.64) 59.53,12.64 59.57,12.68 60.67,12.68 60.68,12.7 J20.29
  BOTTOM w0.2: v1(52.1,12.78) 52.78,12.78 53.15,13.15 53.15,13.36 53.67,13.88 57.82,13.88 v1(59.06,12.64)
AIPL1_LINEIN: length 25.3
  TOP w0.2: J3.3 22.82,9.6 20.9,7.68 15.97,7.68 13.97,9.68 v1(13.2,9.68) ; v1(3.8,9.68) 3.32,10.16 J34.32
  BOTTOM w0.2: v1(13.2,9.68) v1(3.8,9.68)
AIPL1_MIC: length 18.2
  TOP w0.2: J34.28 3.66,15.24 5.1,16.68 9,16.68 9.6,17.28 v1(11.8,17.28) ; U2.1 16.55,15.41 v1(15.78,15.41)
  BOTTOM w0.2: v1(15.78,15.41) 13.67,15.41 v1(11.8,17.28)
AIPR1_LINEIN: length 28.3
  TOP w0.2: J20.31 61.55,10.16 60.75,9.35 60.75,8.8 60.06,8.11 v1(59.1,8.11) ; v1(50.6,7.78) 50.1,7.28 38.4,7.28 37.2,8.48 J23.3
  BOTTOM w0.2: v1(50.6,7.78) 50.93,7.45 58.44,7.45 v1(59.1,8.11)
AIPR1_MIC: length 18.9
  TOP w0.2: U3.1 46.35,12.73 47,13.38 v1(52.6,13.38) ; v1(59.7,13.23) 60.35,13.88 61.7,13.88 62.1,14.28 J20.27
  BOTTOM w0.2: v1(59.7,13.23) 59.03,13.23 57.98,14.28 53.5,14.28 v1(52.6,13.38)
BEVK_3V3: length 10.2
  TOP w0.3: v1(8,51.93) 8.9,51.93 9.15,51.68 10.1,51.68 C40.1
  TOP w0.4: C40.1 10.95,52.53 U4.6
  BOTTOM w0.3: v1(8,51.93) 7.2,51.93 6.55,51.28 4.59,51.28 J56.1
BEVK_SWS: length 11.1
  TOP w0.2: J56.10 7.41,61.16 7.41,54.77 R17.2 9.61,53.98 U4.4
DM: length 19.5
  TOP w0.2: v1(4.15,48.68) 4.48,49.01 4.48,49.26 5.2,49.98 11.8,49.98 13.9,52.08 R8.2 ; J34.2 2.6,48.26 3,48.66 v1(3,48.68)
  BOTTOM w0.2: v1(3,48.68) v1(4.15,48.68)
DMICCK1: length 34.2
  TOP w0.2: v1(28.5,31.78) 28.12,31.4 28.12,31 R9.2 27.13,30.48 27.08,30.53 U6.4 ; J20.8 53.7,40.64 51.14,38.08 v1(42.1,38.08)
  BOTTOM w0.2: v1(42.1,38.08) 34.8,38.08 v1(28.5,31.78)
DMICCK2: length 14.3
  TOP w0.2: U7.4 44.34,39.33 44.39,39.28 R19.2 50.49,39.28 53.29,42.09 55.41,42.09 55.6,42.28 55.6,42.97 J20.6
DMICDAT: length 43.9
  TOP w0.2: U6.5 25.25,31.36 25.25,30.19 25.76,29.68 27,29.68 27.28,29.96 27.96,29.96 29.28,31.28 v1(30.4,31.28) ; J20.10 53.32,38.1 51.78,36.56 v1(41,36.56) 40.4,37.16 40.4,39.66 40.89,40.15 41.94,40.15 42.77,40.98 U7.5
  BOTTOM w0.2: v1(30.4,31.28) 30.4,31.75 35.21,36.56 v1(41,36.56)
DP: length 20.6
  TOP w0.2: J34.4 1.79,45.72 3.6,47.52 3.6,48.95 5.03,50.38 11.63,50.38 13.1,51.85 R10.2
LED_B: length 4.8
  TOP w0.2: R22.1 10.91,24.59 8.9,24.59 8.09,25.4 J34.19
LED_G: length 4.5
  TOP w0.2: J34.21 10.78,22.86 R21.1
LED_R: length 5.3
  TOP w0.2: R20.1 10.9,20.58 8.09,17.78 J34.25
LED_W: length 4.9
  TOP w0.2: R23.1 9.84,20.32 J34.23
MICBIAS_AIL1: length 30
  TOP w0.2: J34.36 2.8,5.08 v1(4,6.28) ; R2.1 22.7,14.88 22.7,13.58 22,12.88 13.7,12.88 11.6,10.78 11.6,7.38 v1(10.5,6.28)
  BOTTOM w0.2: v1(4,6.28) v1(10.5,6.28)
MICBIAS_AIR1: length 15.7
  TOP w0.2: J20.35 57.7,5.08 57.5,5.28 57.5,5.61 57.11,6 54.48,6 52.6,7.88 52.6,9.58 R4.1
TL_AINL1: length 50.6
  TOP w0.2: J34.33 8.96,7.62 9.4,8.05 9.4,10.88 8.9,11.38 7.99,11.38 7.54,11.83 J34.29 8.09,12.7 8.9,13.5 8.9,14.05 9.68,14.84 11.72,14.84 16.91,20.03 16.91,39.23 23.1,45.41 v1(23.1,45.78) 23.1,46.25 23.3,46.45 C19.1
TL_AINR1: length 62.3
  TOP w0.2: C24.1 24.1,45.98 v1(24.3,45.78) ; J20.34 54.26,7.62 53.98,7.9 53.98,10.96 54.4,11.38 55.6,11.38 55.8,11.58 J20.30 55.8,13.57 55.8,13.57 55.8,13.68 55.6,13.88 54.7,13.88 53.74,14.84 50.98,14.84 48.12,17.7 48.12,20.24 45.2,23.16 45.2,27.11 44.28,28.03 35.81,28.03 25.1,38.74 v1(25.1,41.98)
  BOTTOM w0.2: v1(25.1,41.98) 25.1,42.48 24.7,42.88 24.7,45.38 v1(24.3,45.78)
TL_AIPL1: length 48.3
  TOP w0.2: C17.1 22.5,45.38 16.51,39.39 16.51,20.19 11.56,15.24 J34.27 5.96,15.24 5.6,14.88 5.6,10.78 6.22,10.16 J34.31
TL_AIPR1: length 61
  TOP w0.2: v1(25.7,42.48) 25.7,38.71 35.98,28.43 44.45,28.43 45.6,27.28 45.6,23.33 48.52,20.41 48.52,17.86 51.14,15.24 J20.28 57.22,15.24 57.66,14.8 57.66,10.44 57.38,10.16 J20.32 ; v1(24.8,46.28) 24.8,47.18 C25.1
  BOTTOM w0.2: v1(25.7,42.48) 25.13,43.05 25.13,45.95 v1(24.8,46.28)
TL_AONHPL: length 80.4
  TOP w0.2: J24.2 72.4,6.43 71.49,7.34 71.49,10.79 69.25,13.03 69.25,15.76 68.86,16.15 65.03,16.15 64.3,16.88 64.3,18.18 63.6,18.88 60.5,18.88 59.4,17.78 J20.26 54.38,17.78 54.29,17.68 C34.2 R6.2 50.02,19.56 50.02,21.03 47.1,23.95 47.1,28.55 45.72,29.93 36.6,29.93 27.8,38.73 27.8,43.16 29.43,44.79 29.43,48.65 28.3,49.78 U1.26
TL_AONHPR: length 69.8
  TOP w0.2: U1.28 29.1,49.61 29.47,49.25 29.83,48.88 29.83,44.62 28.2,42.99 28.2,38.89 36.76,30.33 45.88,30.33 47.5,28.71 47.5,24.11 50.42,21.2 50.42,20.76 R7.1 C37.1 59.4,19.28 60.44,20.32 J20.23 63.84,20.32 64.8,21.28 70.95,21.28 72.4,19.83 J27.2
TL_AOPHPL: length 68.2
  TOP w0.2: U1.25 27.9,49.61 28.37,49.15 29.03,48.48 29.03,44.95 27.4,43.32 27.4,38.56 36.43,29.53 45.55,29.53 46.7,28.38 46.7,23.78 49.62,20.87 49.62,18.96 R6.1 C34.1 59.4,16.68 60.5,17.78 62.1,17.78 J20.25 62.65,17.78 63.46,16.97 63.64,16.97 66.23,14.38 J24.3
TL_AOPHPR: length 67.5
  TOP w0.2: J27.3 67.5,27.28 67.5,23.18 66,21.68 60.4,21.68 59.04,20.32 J20.24 53.41,20.32 53.37,20.28 C37.2 R7.2 47.9,24.28 47.9,28.88 46.05,30.73 36.98,30.73 28.67,39.04 28.67,42.9 30.23,44.45 30.23,49.05 29.5,49.78 U1.29
TL_AVD: length 11.2
  TOP w0.2: U1.24 27.5,49.44 27.48,49.43
  TOP w0.3: 27.48,49.43 27.48,48.45 28.02,47.91 28.02,47.76 28.2,47.58 C31.1 28.5,48.16 v1(28.48,48.18)
  BOTTOM w0.5: v1(52.9,35.56) 52.9,39.38 54.16,40.64 J51.7
TL_AVDD1V4: length 8.1
  TOP w0.2: U1.46 36.02,52.98 36.79,52.21 37.07,52.21 C16.1 37.73,51.55 39.05,51.55 39.15,51.45 39.77,51.45 v1(40.1,51.78)
  BOTTOM w0.5: J50.8 5.74,40.64 v1(5.7,40.68)
TL_AVDD3: length 8.2
  TOP w0.2: v1(40.4,55.78) 38.98,55.78 38.56,55.36 37.72,55.36 C11.1 36.4,55.88 35.9,55.38 U1.52
  BOTTOM w0.5: J51.14 v1(63.86,33.02)
TL_DVDD1V4: length 9.3
  TOP w0.2: U1.45 35.65,52.58 C22.1 37.72,50.51 37.91,50.51 37.97,50.45 39.59,50.45 39.82,50.68 v1(40.7,50.68)
  BOTTOM w0.5: J50.12 7.52,35.58 5.5,35.58 v1(5.4,35.48)
TL_FLASH: length 49.1
  TOP w0.2: C38.1 49.94,42 R14.1 R15.1 R16.1
  TOP w0.3: SW6.2 60.9,62.73 v1(60.92,62.75)
  TOP w0.4: U10.8 U5.8 ; v1(60.92,62.75) 61.49,62.75 61.51,62.73 SW6.1
  TOP w0.5: U10.8 50.94,44.55 C38.1 50.96,42.98 51.7,42.98 52,43.28 v1(52,44.88) 52,54.4 v1(51.6,54.8) 51.4,55 R13.1 R12.1 R11.1
  BOTTOM w0.3: v1(51.6,54.8) 51.6,55.68 52.9,56.98 54.55,56.98 60.32,62.75 v1(60.92,62.75)
  BOTTOM w0.5: J51.5 53.7,43.18 v1(52,44.88)
TL_FVDD1V8: length 8
  TOP w0.2: v1(40.4,53.81) 39.93,53.81 39.89,53.85 37.73,53.85 C13.1 37,54.58 U1.50
  BOTTOM w0.5: J51.3 v1(53.96,45.72)
TL_IO: length 139.6
  TOP w0.3: J56.7 4.63,58.86 4.63,54.06 5.01,53.68 6.96,53.68 7.86,52.78 8.45,52.78
  TOP w0.5: v1(44.55,42.63) U7.6 43.34,42.63 41.69,40.98 U7.2 40.75,40.98 ; v1(44.55,42.63) 45.05,42.63 C26.1 45.1,42.83 v1(44.67,43.26) 44.55,43.13 v1(44.55,42.63) ; U6.6 26.12,33.88 v1(27.01,33.88) 27.01,34.67 v1(26.8,34.88) 26.08,35.6 25.32,35.6 C23.1 25.28,35.6 v1(22.49,35.6) v1(21.87,35.6) R29.1 ; 8.9,52.78 8.45,52.78 ; 8.9,52.78 v1(9.4,52.28) v1(9.9,52.78) 8.9,52.78 ; v1(71.22,46.7) 71.5,46.98 v1(71.5,47.42) C48.1 71.5,48.95 71.55,48.99 U9.5 ; 40.75,40.98 v1(40.11,40.34) 40.11,40.97 v1(40.1,40.98) 40.75,40.98
  BOTTOM w0.3: 8.9,52.78 v1(9.9,52.78) ; 8.9,52.78 v1(9.4,52.28) ; 8.9,52.78 7.85,52.78 6.88,53.75 5.03,53.75 4.6,54.18 4.6,58.9 J56.7
  BOTTOM w0.5: v1(27.01,33.88) 26.8,34.09 v1(26.8,34.88) 32.9,40.98 39.47,40.98 ; 21.87,36.14 v1(21.87,35.6) v1(22.49,35.6) 21.95,36.14 21.87,36.14 ; 21.87,36.14 11.6,46.41 11.6,46.43 11.1,46.93 11.1,49.48 9.4,51.18 v1(9.4,52.28) v1(9.9,52.78) ; v1(71.22,46.7) 71.2,46.68 71.2,44.28 65.02,38.1 J51.10 ; v1(71.22,46.7) 70.78,47.14 ; v1(71.22,46.7) 71.22,47.14 ; 71.22,47.14 v1(71.5,47.42) ; 71.22,47.14 70.78,47.14 ; 45.18,43.26 46.98,43.26 49.7,45.98 49.7,49.48 51.04,50.82 67.08,50.82 70.76,47.14 70.78,47.14 ; 45.18,43.26 v1(44.67,43.26) 44.55,43.13 v1(44.55,42.63) 45.18,43.26 ; 39.47,40.98 v1(40.11,40.34) 40.11,40.97 v1(40.1,40.98) 39.47,40.98
TL_KEY1: length 41.9
  TOP w0.2: SW2.1 SW2.2 SW3.1 SW3.2 43.97,26.53 44.22,26.28 v1(44.22,25.66) ; v1(57.8,27.88) 57.8,29.48 58.8,30.48 J20.15
  BOTTOM w0.2: v1(57.8,27.88) 57.8,27.48 57.34,27.02 52.24,27.02 50.9,25.68 44.7,25.68 44.69,25.66 v1(44.22,25.66)
TL_KEY2: length 44.5
  TOP w0.2: J20.17 58.96,27.94 v1(58.5,27.48) ; SW4.1 SW4.2 SW5.1 SW5.2 43,19.05 42.9,19.15 v1(42.9,20.23)
  BOTTOM w0.2: v1(58.5,27.48) 58.17,27.15 58.03,27.15 57.5,26.62 52.4,26.62 51.07,25.28 45.9,25.28 42.9,22.28 v1(42.9,20.23)
TL_KEY3: length 60.3
  TOP w0.2: v1(44.33,21.94) 44.33,22.74 43.29,23.78 34.25,23.78 32.5,22.03 SW2.4 SW2.3 23.8,22.03 22.82,21.05 22.82,17.1 23.14,16.77 23.14,14.49 23.8,13.83 SW4.3 SW4.4 ; J20.19 59.92,25.4 59,24.48 59,22.58 v1(58.6,22.18)
  BOTTOM w0.2: v1(58.6,22.18) 58.13,22.18 57.89,21.94 v1(44.33,21.94)
TL_KEY4: length 45.6
  TOP w0.2: SW5.3 SW5.4 43.25,13.83 44.19,14.77 44.19,19.9 v1(43.85,20.23) 43,21.09 SW3.4 SW3.3 ; v1(59.26,21.54) 59.26,22.24 59.88,22.86 J20.21 62.08,22.88
  BOTTOM w0.2: v1(43.85,20.23) 44.28,20.66 44.28,20.82 45,21.54 v1(59.26,21.54)
TL_MICBIAS: length 103.6
  TOP w0.2: J20.36 32.7,5.08 31,3.38 27.5,3.38 27,3.88 14.4,3.88 13.2,5.08 J34.35 7.54,6.02 7.9,6.38 8.8,6.38 10,7.58 10,11.56 18.21,19.77 18.21,38.76 25.42,45.97 25.42,50.3 25.6,50.48 U1.20
TL_PA0_I2SCLK: length 40.3
  TOP w0.2: J34.10 1.79,38.1 2.79,39.09 8.23,39.09 10.21,41.07 10.21,42.03 15.7,47.52 v1(15.7,49.98) ; v1(28.5,58.28) 28.3,58.48 U1.75
  BOTTOM w0.2: v1(15.7,49.98) 16.88,49.98 17.65,50.75 17.65,53.4 21.58,57.33 27.43,57.33 28.05,57.95 28.17,57.95 v1(28.5,58.28)
TL_PA1_SPI_SLV_CN: length 38.7
  TOP w0.2: J34.11 8.09,35.56 10.1,37.56 10.1,39.27 11.41,40.58 11.41,41.53 17.65,47.77 17.65,53.43 v1(16.7,54.38) ; v1(22,60.5) 22.47,60.5 22.62,60.35 27.31,60.35 27.9,59.76 U1.76
  BOTTOM w0.2: v1(22,60.5) 21.58,60.08 21.58,59.46 17.3,55.18 17.3,55.01 17.03,54.74 17.03,54.71 v1(16.7,54.38)
TL_PA2_SPI_SLV_CK: length 33.7
  TOP w0.2: v1(27.6,58.28) 27.5,58.38 U1.77 ; v1(16.7,50.58) 16.7,47.95 10.61,41.86 10.61,40.91 9.2,39.5 9.2,38.28 9.02,38.1 J34.9
  BOTTOM w0.2: v1(27.6,58.28) 27.27,57.95 27.17,57.95 26.95,57.73 21.42,57.73 17.25,53.56 17.25,51.15 16.7,50.6 v1(16.7,50.58)
TL_PA3_SPI_SLV_DI: length 46.7
  TOP w0.2: U1.78 27.1,59.76 26.91,59.95 v1(21.03,59.95) ; J34.14 1.79,33.02 2.6,33.82 2.6,34.37 2.86,34.64 8.85,34.64 9.1,34.88 9.1,36 10.5,37.4 10.5,39.1 11.81,40.41 11.81,41.36 18.05,47.6 18.05,53.93 v1(16.75,55.23)
  BOTTOM w0.2: v1(16.75,55.23) 17.26,55.75 17.3,55.75 21.03,59.48 v1(21.03,59.95)
TL_PA4_SPI_SLV_DO: length 41.4
  TOP w0.2: J34.12 1.88,35.56 3.5,37.18 8.9,37.18 9.7,37.98 9.7,39.43 11.01,40.74 11.01,41.7 17.25,47.93 17.25,50.83 v1(16.7,51.38) ; v1(26.72,58.28) 26.7,58.3 U1.79
  BOTTOM w0.2: v1(26.72,58.28) 21.4,58.28 16.7,53.58 v1(16.7,51.38)
TL_PA5_DM: length 25.9
  TOP w0.2: J34.1 11.63,48.26 15.05,51.67 15.05,56.46 15.12,56.53 15.12,57.84 15.86,58.58 U1.1
TL_PA6_DP: length 26.6
  TOP w0.2: J34.3 9.66,45.72 15.45,51.51 15.45,56.29 15.52,56.36 15.52,57.4 16.3,58.18 U1.2
TL_PA7_SWS: length 19.6
  TOP w0.2: R17.1 v1(9.6,54.98) 9.65,55.03 U4.3 ; U1.3 17.8,57.78 v1(16.8,56.78)
  BOTTOM w0.2: v1(9.6,54.98) 10.6,54.98 12.4,56.78 v1(16.8,56.78)
TL_PB0: length 41.8
  TOP w0.2: U1.4 22.1,57.38 18.45,53.73 18.45,47.44 16,44.98 12.21,41.2 12.21,40.25 10.9,38.93 10.9,37.56 10.9,37.23 9.5,35.83 9.5,34.72 9.02,34.24 5.66,34.24 3,31.58 3,30.88 2.6,30.48 1.25,30.48 J34.16
TL_PB1: length 34.2
  TOP w0.2: U1.5 22.27,56.98 18.85,53.56 18.85,47.27 16.53,44.95 12.61,41.03 12.61,40.08 11.3,38.77 11.3,37.73 11.3,37.07 9.9,35.67 9.9,34.55 9.11,33.76 9.11,33.17 8.96,33.02 J34.13
TL_PB2_I2CSCK: length 43.2
  TOP w0.2: J34.18 1.39,28.08 2.7,28.08 3.3,28.68 3.3,28.75 4.15,29.6 4.15,30.53 5.72,32.1 8.85,32.1 9.42,32.66 9.42,32.91 9.51,33 9.51,33.6 10.3,34.38 10.3,35.5 11.7,36.9 11.7,37.9 11.7,38.6 13.01,39.91 13.01,40.87 14.97,42.83 17.22,45.08 19.25,47.11 19.25,53.4 22.43,56.58 U1.6
TL_PB3_I2CSDA: length 35.3
  TOP w0.2: U1.7 22.6,56.18 19.65,53.23 19.65,46.94 18.75,46.04 17.51,44.8 13.41,40.7 13.41,39.75 12.1,38.44 12.1,38.06 12.1,36.74 10.7,35.33 10.7,34.22 9.91,33.43 9.91,32.84 9.82,32.74 9.82,32.5 9.3,31.97 9.3,31.68 8.09,30.48 J34.15
TL_PB4: length 44.8
  TOP w0.2: U1.11 23.54,54.58 23.22,54.26 21.78,54.26 20.05,52.53 20.05,46.77 19.03,45.75 17.79,44.51 13.81,40.54 13.81,39.58 12.5,38.27 12.5,38.23 12.5,36.57 11.1,35.17 11.1,34.05 10.31,33.27 10.31,32.67 10.22,32.58 10.22,32.33 9.7,31.81 9.7,30.28 8.98,29.56 4.68,29.56 3.7,28.58 3.7,26.18 2.9,25.38 2.68,25.38 2.66,25.4 J34.20
TL_PB5: length 46.9
  TOP w0.2: J34.22 2.98,22.86 3.4,23.28 3.4,25.31 4.13,26.05 4.13,28.45 4.84,29.16 9.14,29.16 10.1,30.11 10.1,31.64 10.38,31.93 10.62,32.16 10.62,32.41 10.71,32.5 10.71,33.1 11.5,33.89 11.5,35 12.9,36.4 12.9,38.11 14.21,39.42 14.21,40.37 18.07,44.23 20.45,46.61 20.45,52.36 21.79,53.7 23.48,53.7 23.96,54.18 U1.12
TL_PB6: length 47.3
  TOP w0.2: J34.24 1.79,20.32 3.9,22.42 3.9,24.68 6.24,27.02 8.99,27.02 10.5,28.53 10.5,31.48 10.55,31.53 11.02,32 11.02,32.24 11.11,32.34 11.11,32.94 11.9,33.72 11.9,34.84 13.3,36.24 13.3,37.94 14.61,39.25 14.61,39.58 14.61,40.2 18.36,43.95 20.85,46.44 20.85,52.2 21.95,53.3 23.64,53.3 24.12,53.78 U1.13
TL_PB7: length 49.9
  TOP w0.2: U1.14 24.29,53.38 23.81,52.9 22.12,52.9 21.25,52.03 21.25,46.28 18.64,43.67 15.01,40.04 15.01,39.75 15.01,39.09 13.7,37.77 13.7,36.07 12.3,34.67 12.3,33.56 11.51,32.77 11.51,32.17 11.42,32.08 11.42,31.83 10.9,31.31 10.9,28.36 9.15,26.62 6.4,26.62 4.3,24.51 4.3,19.38 2.7,17.78 2.67,17.78 2.66,17.78 J34.26
TL_PC0: length 43.6
  TOP w0.2: v1(29.64,51.16) 29.9,50.89 U1.30 ; v1(30.72,42.05) 30.72,39.68 37.21,33.19 37.62,32.78 49.81,32.78 53.95,28.64 53.95,28.23 54.24,27.94 J20.18
  BOTTOM w0.2: v1(29.64,51.16) 30.8,49.99 30.8,45.86 31.35,45.31 31.35,44.23 30.72,43.6 v1(30.72,42.05)
TL_PC1: length 47.3
  TOP w0.2: U1.31 30.3,49.66 30.63,49.33 30.63,46.1 31.4,45.33 31.4,44.07 29.77,42.44 29.77,39.5 37.29,31.98 49.48,31.98 53.15,28.31 53.15,27.9 53.65,27.4 53.65,23.53 54.3,22.88 54.36,22.88 54.38,22.86 J20.22
TL_PC2: length 41.5
  TOP w0.2: U1.32 30.7,50.98 v1(30.5,51.18) ; J20.16 55.4,30.88 54.3,30.88 52,33.18 37.79,33.18 37.38,33.59 31.27,39.69 v1(31.27,42.58)
  BOTTOM w0.2: v1(30.5,51.18) 31.2,50.48 31.2,46.02 31.75,45.47 31.75,43.06 v1(31.27,42.58)
TL_PC3_I2SBCK: length 44.6
  TOP w0.2: U1.33 31.1,48.96 31.03,48.89 31.03,46.27 31.8,45.5 31.8,43.9 30.29,42.39 30.17,42.28 30.17,39.66 37.46,32.38 49.64,32.38 53.55,28.47 53.55,28.06 54.05,27.56 54.05,25.63 54.3,25.38 55.79,25.38 J20.20
TL_PC4_ADC_LR: length 46.3
  TOP w0.2: J20.13 59.14,33.02 58.1,31.98 54.1,31.98 52.5,33.58 37.95,33.58 37.54,33.99 33.68,37.86 32.35,39.18 v1(32.35,44.18) ; v1(32.85,51.18) 32.7,51.03 U1.37
  BOTTOM w0.2: v1(32.85,51.18) 32.85,44.68 v1(32.35,44.18)
TL_PC5_ADC_DAT: length 37
  TOP w0.2: J20.14 55.24,33.58 54,33.58 53.6,33.98 38.12,33.98 37.71,34.39 33.96,38.14 32.75,39.35 32.75,43.53 33.4,44.18 33.4,49.03 33.1,49.33 U1.38
TL_PC6_DAC_LR: length 42.7
  TOP w0.2: J20.11 62.03,35.48 59.5,35.48 58.4,34.38 38.28,34.38 34.24,38.42 33.15,39.51 33.15,43.36 33.8,44.01 33.8,49.19 33.5,49.49 U1.39
TL_PC7_DAC_DAT: length 33.7
  TOP w0.2: J20.12 55.43,35.18 54.4,35.18 54,34.78 52.8,34.78 52.31,35.27 40.33,35.27 38.85,36.75 38.85,42.65 34.35,47.15 34.2,47.3 34.2,49.36 33.9,49.66 U1.40
TL_PD0_32K: length 7.1
  TOP w0.2: U1.53 35.73,55.78 37.78,57.83 38.88,57.83 39.53,57.18 J30.2
TL_PD1_32K: length 7.5
  TOP w0.2: U1.54 35.57,56.18 37.62,58.23 38.95,58.23 J31.2
TL_PD2: length 39.6
  TOP w0.2: J20.4 57.34,45.72 59,47.38 59,53.88 52.9,59.98 46.5,59.98 45.45,61.03 39.75,61.03 35.3,56.58 U1.55
TL_PD3: length 38.3
  TOP w0.2: J20.2 57.48,48.26 58.6,49.38 58.6,53.68 52.7,59.58 45.9,59.58 v1(45.3,60.18) ; U1.56 v1(33.6,56.98)
  BOTTOM w0.2: v1(45.3,60.18) 44.45,61.03 40.12,61.03 36.07,56.98 v1(33.6,56.98)
TL_PD4_DMICDAT: length 47.5
  TOP w0.2: J20.9 62.09,38.08 60.6,38.08 59.4,39.28 59.4,54.08 53.1,60.38 46.67,60.38 45.62,61.43 39.58,61.43 35.53,57.38 U1.57
TL_PD5_DMICCLK1: length 45.4
  TOP w0.2: U1.58 35.27,57.78 39.32,61.83 45.78,61.83 46.83,60.78 53.27,60.78 59.8,54.25 59.8,41.48 60.64,40.64 J20.7
TL_PD6_DMICCLK2: length 43.4
  TOP w0.2: U1.59 35.1,58.18 39.15,62.23 45.95,62.23 47,61.18 53.43,61.18 60.2,54.41 60.2,43.68 60.7,43.18 62.1,43.18 J20.5
TL_PD7: length 40.8
  TOP w0.2: J20.3 61.55,45.72 60.6,46.67 60.6,54.58 53.6,61.58 47.16,61.58 46.11,62.63 38.95,62.63 34.9,58.58 U1.60
TL_PE0_UART1_TX: length 34.7
  TOP w0.2: J34.5 9.1,43.18 13.29,47.37 v1(13.29,47.59) ; v1(32.4,58.28) 32.2,58.48 31.8,58.48 31.5,58.78 U1.67
  BOTTOM w0.2: v1(32.4,58.28) 32.4,57.81 32.15,57.56 32.15,57.53 30.35,55.73 22.24,55.73 19.25,52.74 19.25,50.09 16.75,47.59 v1(13.29,47.59)
TL_PE1_UART1_CTS: length 43
  TOP w0.2: U1.68 31.1,60.03 v1(31,60.13) ; v1(13.9,48.18) 13.9,47.41 9.01,42.52 9.01,42.41 8.85,42.26 2.71,42.26 1.79,43.18 J34.6
  BOTTOM w0.2: v1(13.9,48.18) 16.77,48.18 18.85,50.25 18.85,52.9 22.08,56.13 30.19,56.13 31.75,57.69 31.75,59.38 v1(31,60.13)
TL_PE2_UART1_RTX: length 41.2
  TOP w0.2: v1(31.2,58.28) 30.7,58.78 U1.69 ; J34.8 1.79,40.64 3.01,41.86 9.02,41.86 9.41,42.25 9.41,42.36 14.45,47.4 14.45,48.26 14.44,48.27 v1(14.44,48.74)
  BOTTOM w0.2: v1(31.2,58.28) 31.2,57.71 30.02,56.53 21.91,56.53 18.45,53.07 18.45,50.42 16.76,48.73 14.92,48.73 14.91,48.74 v1(14.44,48.74)
TL_PE3_UART1_RTS: length 57.9
  TOP w0.2: U1.70 30.3,59.98 v1(30.15,60.13) ; v1(4.4,39.83) 6.19,39.83 6.99,40.64 J34.7 8.96,40.64 9.81,41.49 9.81,42.19 15,47.38 v1(15,49.28)
  BOTTOM w0.2: v1(30.15,60.13) 30.65,59.63 30.65,58.05 29.53,56.93 21.75,56.93 18.05,53.23 18.05,50.59 16.74,49.28 v1(15,49.28) ; J57.1 J57.3 6.46,31.42 4.4,33.48 v1(4.4,39.83)
TL_PE4_TDI: length 28.4
  TOP w0.2: v1(8,64.68) 7.5,65.18 J56.12 ; U1.71 29.9,58.48 v1(30.1,58.28)
  BOTTOM w0.2: v1(30.1,58.28) 29.15,59.23 24.62,59.23 18.77,65.08 8.4,65.08 v1(8,64.68)
TL_PE5_TDO: length 30
  TOP w0.2: U1.72 29.5,59.83 v1(29.2,60.13)
  BOTTOM w0.2: J56.11 4.74,66.53 7.93,66.53 8.58,65.88 19.1,65.88 24.3,60.68 28.65,60.68 v1(29.2,60.13)
TL_PE6_TMS: length 34.2
  TOP w0.2: U1.73 29.1,58.48 v1(29.3,58.28)
  BOTTOM w0.2: v1(29.3,58.28) 28.75,58.83 24.45,58.83 18.6,64.68 10.3,64.68 7.74,62.12 7.74,56.83 J56.4
TL_PE7_TCK: length 32.5
  TOP w0.2: U1.74 28.7,59.83 v1(28.4,60.13)
  BOTTOM w0.2: v1(28.4,60.13) 24.28,60.13 18.93,65.48 7.8,65.48 7.22,64.9 7.22,58.84 J56.6
TL_PF0_MOSI: length 28.6
  TOP w0.2: v1(42.4,46.28) 46.15,46.28 46.15,46.26 46.61,45.8 U5.5 U10.5 47.13,43.48 47.14,43.47 R16.2 ; v1(26.6,55.18) 26.6,55.4 26.22,55.78 U1.8
  BOTTOM w0.2: v1(26.6,55.18) 33.5,55.18 v1(42.4,46.28)
TL_PF1_MCLK: length 38.4
  TOP w0.2: v1(40.6,46.58) 40.6,46.2 41.07,45.73 41.53,45.73 41.85,46.05 41.85,46.6 42.15,46.91 47.77,46.91 48.4,46.28 U5.6 U10.6 48.4,43.51 48.44,43.47 R15.2 ; v1(22.34,55.04) 22.67,55.38 U1.9
  BOTTOM w0.2: v1(40.6,46.58) 40.6,46.95 40.47,47.08 33.32,54.23 22.68,54.23 22.34,54.57 v1(22.34,55.04)
TL_PF2_MSIO3: length 37.6
  TOP w0.2: v1(41.3,46.28) 41.3,46.76 41.88,47.33 48.61,47.33 49.67,46.28 U5.7 U10.7 49.67,43.51 49.64,43.47 R14.2 ; v1(23,54.81) 23.17,54.98 U1.10
  BOTTOM w0.2: v1(23,54.81) 23.47,54.81 23.65,54.63 33.48,54.63 34.12,54 41.3,46.81 v1(41.3,46.28)
TL_PF3_MSCN: length 52
  TOP w0.2: U5.1 50.94,50.18 49.94,49.18 46.57,49.18 44.07,51.68 42.17,51.68 41.73,52.11 41.39,52.46 39.27,52.46 39.08,52.65 36.92,52.65 36.19,53.38 U1.47
  TOP w0.4: R13.2 50.94,53.33 v1(50.94,53.33) U10.1 U5.1 ; SW6.3 66.45,67.23 64.5,65.28 v1(63.38,65.28) 60.93,65.28 59.8,66.41 SW6.4
  BOTTOM w0.3: v1(63.38,65.28) 63.38,62.39 62.27,61.28 59.7,61.28 55,56.58 55,55.98 52.35,53.33 v1(50.94,53.33)
TL_PF4_MISO: length 21
  TOP w0.2: U1.48 36.35,53.78 37.08,53.05 39.24,53.05 39.43,52.86 41.55,52.86 42.33,52.08 44.23,52.08 46.73,49.58 49.17,49.58 49.67,50.08 U5.2
  TOP w0.4: R12.2 49.67,53.97 U10.2 U5.2
TL_PF5_MSIO2: length 19.5
  TOP w0.2: U1.49 36.52,54.18 37.25,53.45 39.41,53.45 39.6,53.26 41.72,53.26 42.5,52.48 44.4,52.48 46.9,49.98 48.18,49.98 48.4,50.21 U5.3
  TOP w0.4: R11.2 48.4,53.94 U10.3 U5.3
TL_RFVDD1V4: length 6.5
  TOP w0.2: 32.48,60.48 32.48,60.33 32.7,60.11 U1.64
  TOP w0.4: 32.48,60.48 32.48,60.7 31.59,61.59 C2.1 C3.1 30.32,61.76 v1(30.1,61.98)
  BOTTOM w0.5: v1(5.6,43.18) 7.54,43.18 J50.6
TL_RST: length 41.2
  TOP w0.2: U1.61 35,59.28 38.75,63.03 44.48,63.03 C10.1 45.26,63.03 46.63,63.03 46.93,62.73 SW1.2 SW1.1 56.1,59.68 61,54.78 61,51.28 62.1,50.18 J20.1
TL_VBAT: length 15.2
  TOP w0.2: 35.45,50.73 35.27,50.91 35.27,51.21 35.1,51.38 U1.42
  TOP w0.3: 35.45,50.73 35.63,50.55 35.63,49.3 C21.1 35.85,49.13 v1(36.2,49.48)
  BOTTOM w0.5: v1(53.7,30.48) J51.15 56.35,30.48 58.8,32.92 58.8,34.68 59.68,35.56 J51.12
TL_VBAT_ADJ: length 24.9
  TOP w0.5: U8.4 U8.2 C45.1 ; R24.2 69.6,33.98 C45.1 ; C45.1 71,34.78 71.71,34.07 71.71,31.29 70.8,30.38 v1(64,30.38)
  BOTTOM w0.5: v1(64,30.38) 62.2,30.38 J51.16
TL_VBUS: length 4.6
  TOP w0.2: U1.41 34.6,50.66
  TOP w0.3: C62.1 34.8,49.08 v1(35.1,48.78)
  TOP w0.4: 34.6,50.66 34.8,50.46 34.8,49.13 C62.1
  BOTTOM w0.5: J50.1 1.72,48.26 2.1,47.88 v1(2.1,46.82)
TL_VDD1V4_O: length 4
  TOP w0.5: L4.2 40.6,49.98 40.99,49.98 41.09,50.08 C29.1 v1(42.1,50.08)
  BOTTOM w0.5: v1(5.7,38.08) 7.53,38.08 J50.10
TL_VDD1V8_O: length 4.1
  TOP w0.5: v1(43.5,55.28) C12.1 42,55.28 L3.2
  BOTTOM w0.5: J51.1 v1(53.92,48.26)
TL_VDD3_DCDC: length 6.9
  TOP w0.2: 35.85,51.03 35.67,51.22 35.67,51.38 35.27,51.78 U1.43
  TOP w0.3: 35.85,51.03 36.13,50.76 36.13,50.44 37,49.57 C15.1 v1(37.7,48.38)
  BOTTOM w0.5: J51.13 v1(54,33.02)
TL_VDD25EF: length 4.9
  TOP w0.2: U1.15 24.46,52.98 23.86,52.38 23.5,52.38 C14.1 22.5,51.38 J52.1
TL_VDDCORE: length 4.4
  TOP w0.2: v1(32.1,47.88) 31.7,48.28 C32.1 31.5,48.58 U1.34
  BOTTOM w0.5: J50.14 v1(5.8,33.02)
TL_VDDDEC: length 3.4
  TOP w0.2: U1.35 31.9,49.66 v1(32.28,49.28) 32.8,48.76 C33.1
  BOTTOM w0.5: J50.13 1.1,32.87 v1(1.1,31.78)
TL_XC1: length 11.7
  TOP w0.2: U1.65 32.3,59.94 31.95,60.29 31.95,60.52 31.32,61.15 27.4,61.15 27.01,61.54 27.01,61.77 C1.2 26.18,62.6 26.18,64.51 27.32,65.64 27.36,65.64
TL_XC2: length 9.8
  TOP w0.2: U1.66 31.9,59.78 31.55,60.13 31.55,60.36 31.16,60.75 27.03,60.75 C4.2 25.6,62.95 Y1.1
VCOM: length 25.1
  TOP w0.5: R26.2 v1(68.1,33.48) R27.1
  BOTTOM w0.5: 58.6,28.98 58.6,31.28 59.9,32.58 59.9,33.59 60.5,34.19 65.19,34.19 65.9,33.48 v1(68.1,33.48) ; 58.6,28.98 58.6,28.38 59.34,27.64 59.34,26.22 58.52,25.4 J51.19 ; 58.6,28.98 58.55,28.93 57.35,28.93 56.35,27.94 J51.17
VDW: length 15.9
  TOP w0.5: R27.2 R28.1 v1(66.6,31.98)
  BOTTOM w0.5: 64.48,25.48 64.48,23.56 63.78,22.86 J51.22 ; 64.48,25.48 64.4,25.4 J51.20 ; 64.48,25.48 64.48,27.76 66.6,29.88 v1(66.6,31.98)
VUP: length 14.7
  TOP w0.5: R25.2 R26.1 66.48,33.98 65.9,33.4 v1(65.9,32.58)
  BOTTOM w0.5: J51.18 60.34,27.94 60.1,28.18 60.1,31.18 60.6,31.68 65,31.68 v1(65.9,32.58)
N19754780: length 3.8
  TOP w0.2: J26.3 14.73,59.58 14.17,59.01 13.46,59.01 13.1,58.65 R10.1
N19754798: length 3.4
  TOP w0.2: R8.1 15.53,59.81 J26.2
N19860865: length 9.2
  TOP w0.2: C8.2 48.54,56.12 Y2.1 46.34,56.28 R1.1 44.4,57.18 J30.1
N19860867: length 6.5
  TOP w0.2: C9.2 47.34,58.48 Y2.2 46.14,57.28 R1.2 44.15,58.43 44.15,58.87 J31.1
N19861195: length 5.2
  TOP w0.2: U1.18 24.95,51.78 24.53,51.36 24.53,48.88 24.1,48.45 C24.2
N19861200: length 3.7
  TOP w0.2: U1.19 25.12,51.38 24.93,51.19 24.93,48.31 C25.2
N19861219: length 12.9
  TOP w0.2: J53.1 23.1,42.09 26.63,45.62 26.63,46.71 C30.1 26.95,47.73 26.95,49.53 27.1,49.68 U1.23
N19861425: length 5.3
  TOP w0.2: U1.17 24.79,52.18 24.13,51.52 24.13,49.11 C19.2
N19861431: length 7.1
  TOP w0.2: U1.16 24.62,52.58 23.73,51.69 23.73,49.31 23.3,48.88 22.93,48.88 22.5,48.45 C17.2
N19861467: length 2.8
  TOP w0.2: C27.1 25.95,49.03 26.3,49.38 U1.21
N19861531: length 5
  TOP w0.2: U1.51 37.53,54.98 37.55,54.96 39.32,54.96 L3.1
N19861571: length 4.9
  TOP w0.2: U1.44 35.43,52.18 36.07,51.54 36.07,51.52 36.16,51.44
  TOP w0.3: 36.16,51.44 36.63,50.96 36.63,50.65 37.22,50.06 37.72,50.06 L4.1
N19870648: length 3.2
  TOP w0.5: R24.1 R25.1 U8.1
N19912632: length 2.4
  TOP w0.2: U3.4 48.7,12.01 48.93,11.78 R4.2 C42.1
N19912698: length 2.4
  TOP w0.2: U2.4 19.77,16.31 20,16.08 R2.2 C41.1
N19916631: length 4.2
  TOP w0.5: J57.4 20.29,31.59 R29.2
N19927561: length 16
  BOTTOM w0.5: J50.5 1.25,43.18 2.8,43.18 3.52,42.46 3.52,40.68 ; 3.52,40.68 3.47,40.64 J50.7 ; 3.52,40.68 3.52,38.18 ; J50.11 2.81,35.56 3.52,36.26 3.52,38.18 ; 3.52,38.18 3.43,38.1 J50.9
N19931796: length 16.7
  BOTTOM w0.5: 64.53,45.78 64.53,47.55 63.82,48.26 J51.2 ; 64.53,45.78 64.47,45.72 J51.4 ; 64.53,45.78 64.53,43.18 ; J51.6 63.9,43.18 63.9,43.18 64.53,43.18 ; 64.53,43.18 64.53,41.25 64.53,41.11 64.06,40.64 J51.8
